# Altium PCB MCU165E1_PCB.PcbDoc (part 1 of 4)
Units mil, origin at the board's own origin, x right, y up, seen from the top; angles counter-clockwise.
Board outline 2658.83 x 2179.35 mil, 6 copper layers (Top Signal Layer, GND1, Mid Layer, PWR, GND2, Bottom Signal Layer), stack 60.4 mil thick; 226 components, 197 nets, 947 pads, 562 vias.
Unrouted connection lines stored in the file: 81.
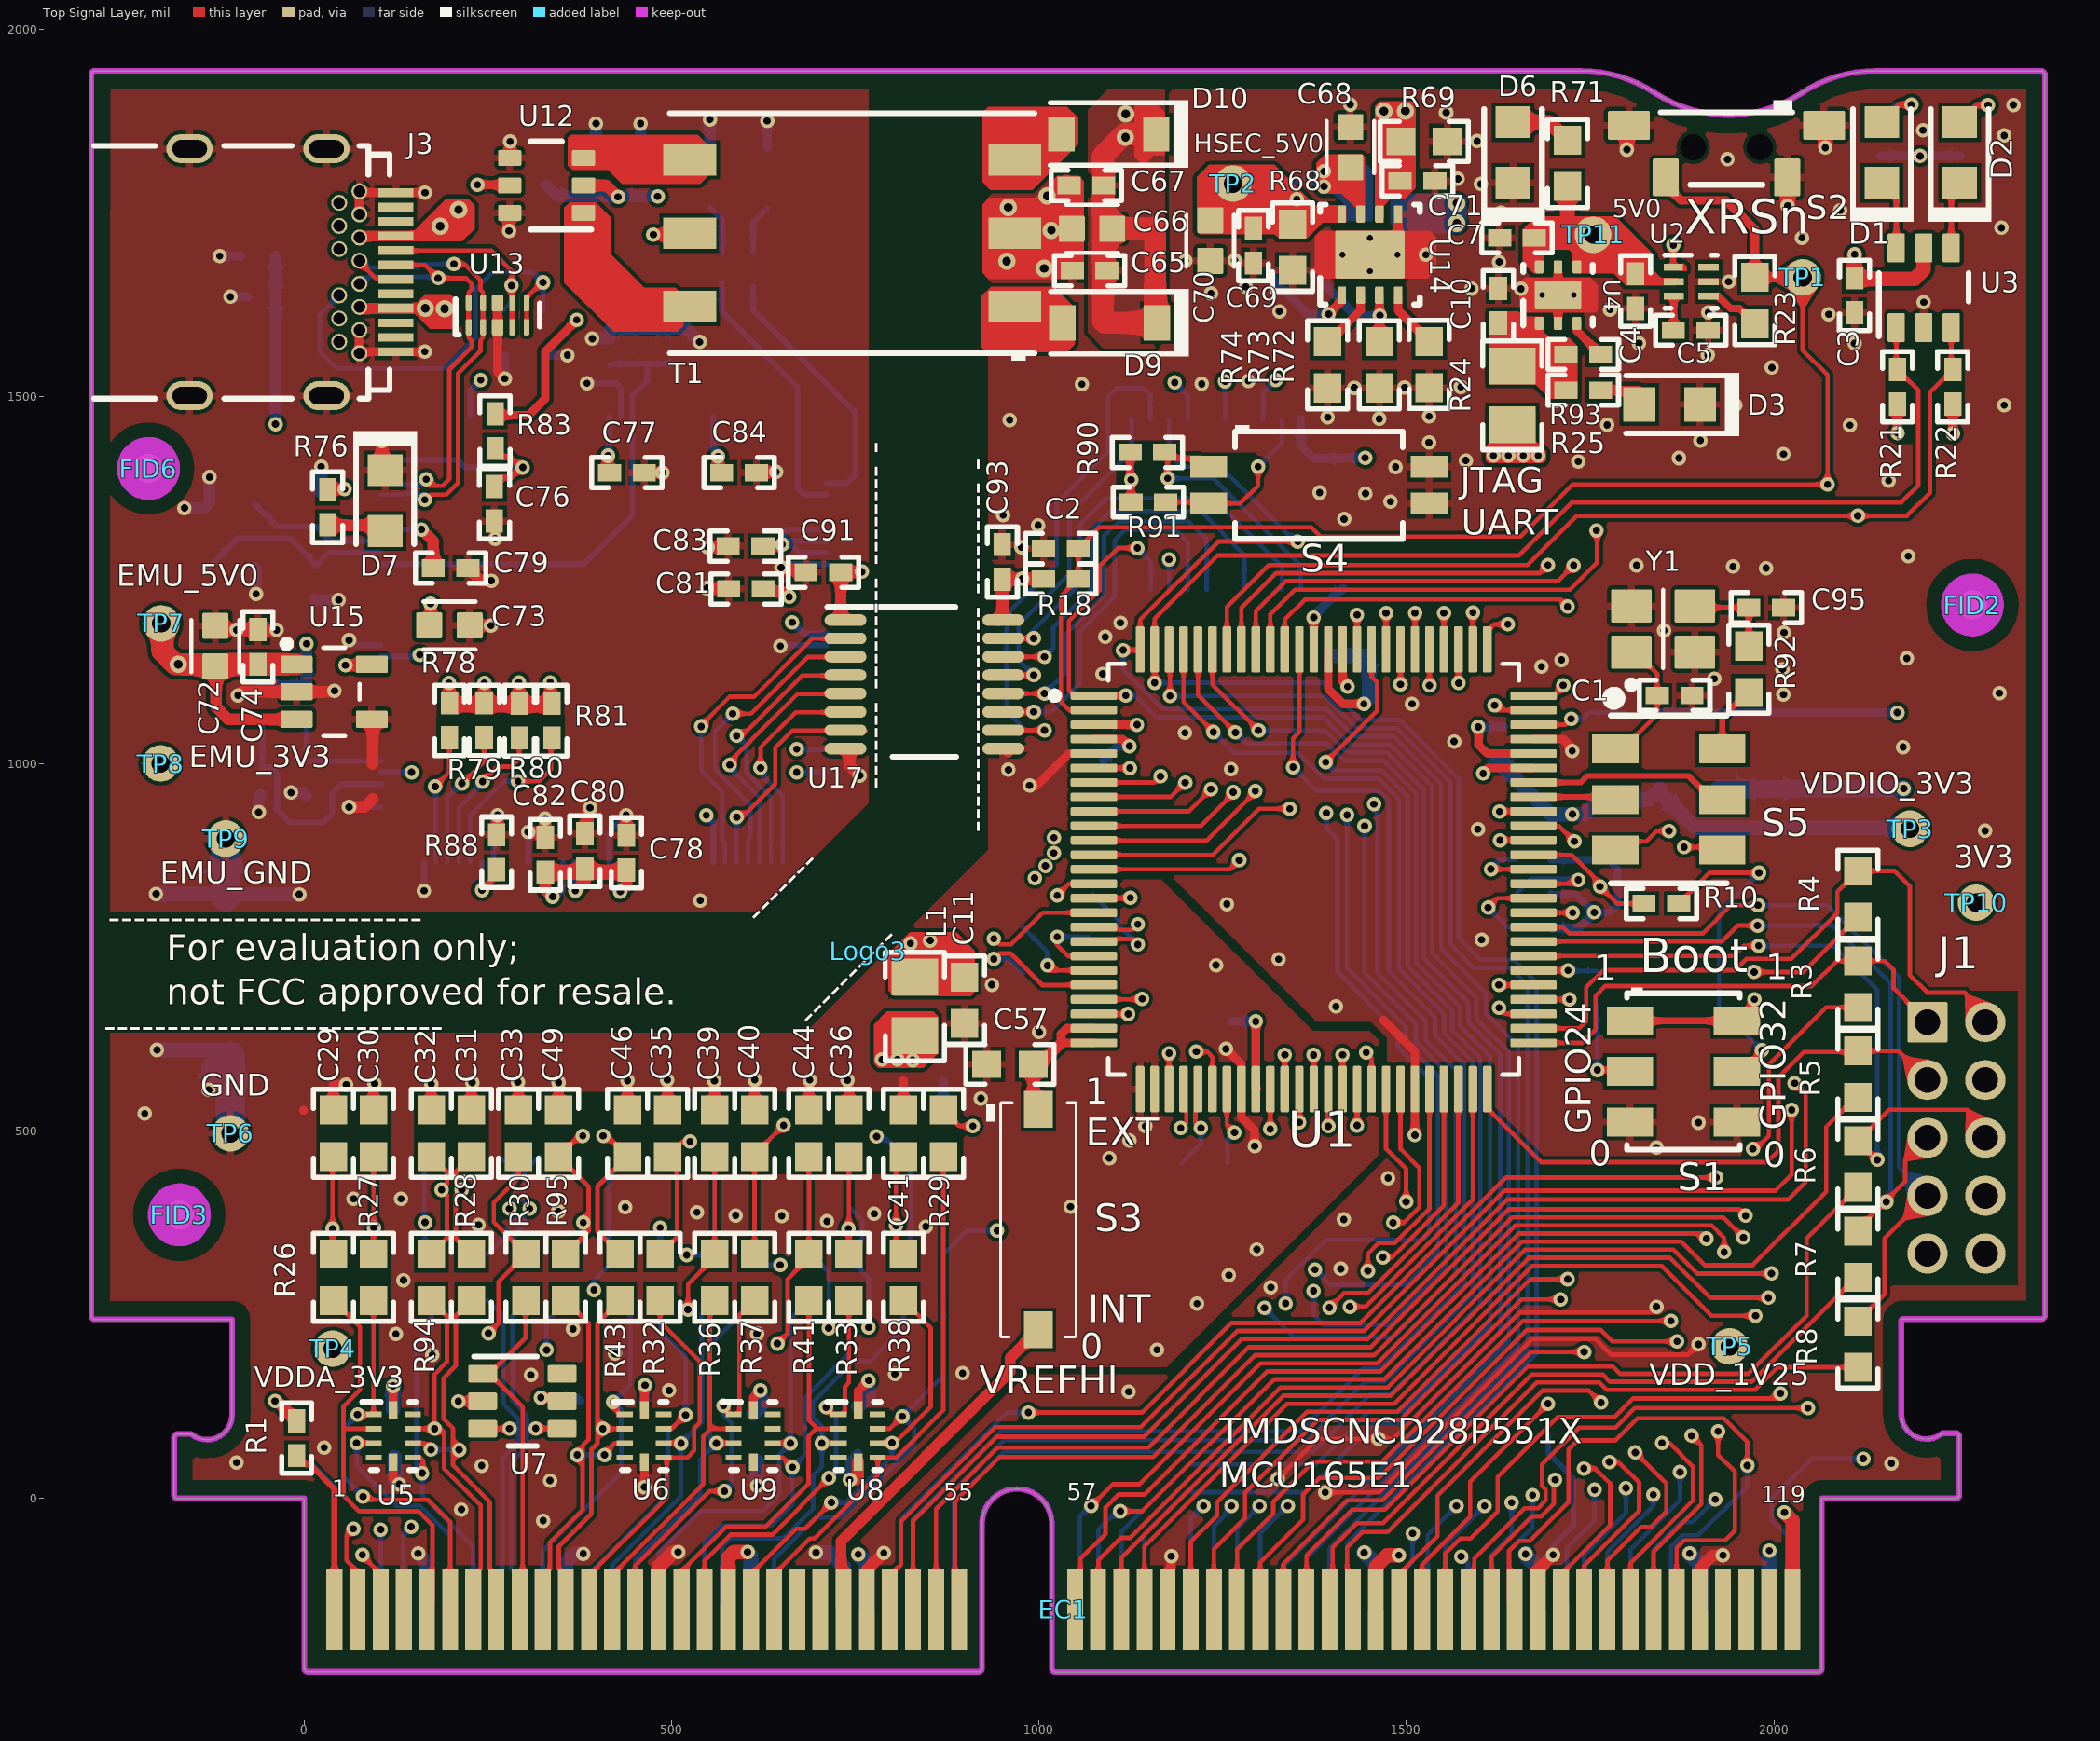
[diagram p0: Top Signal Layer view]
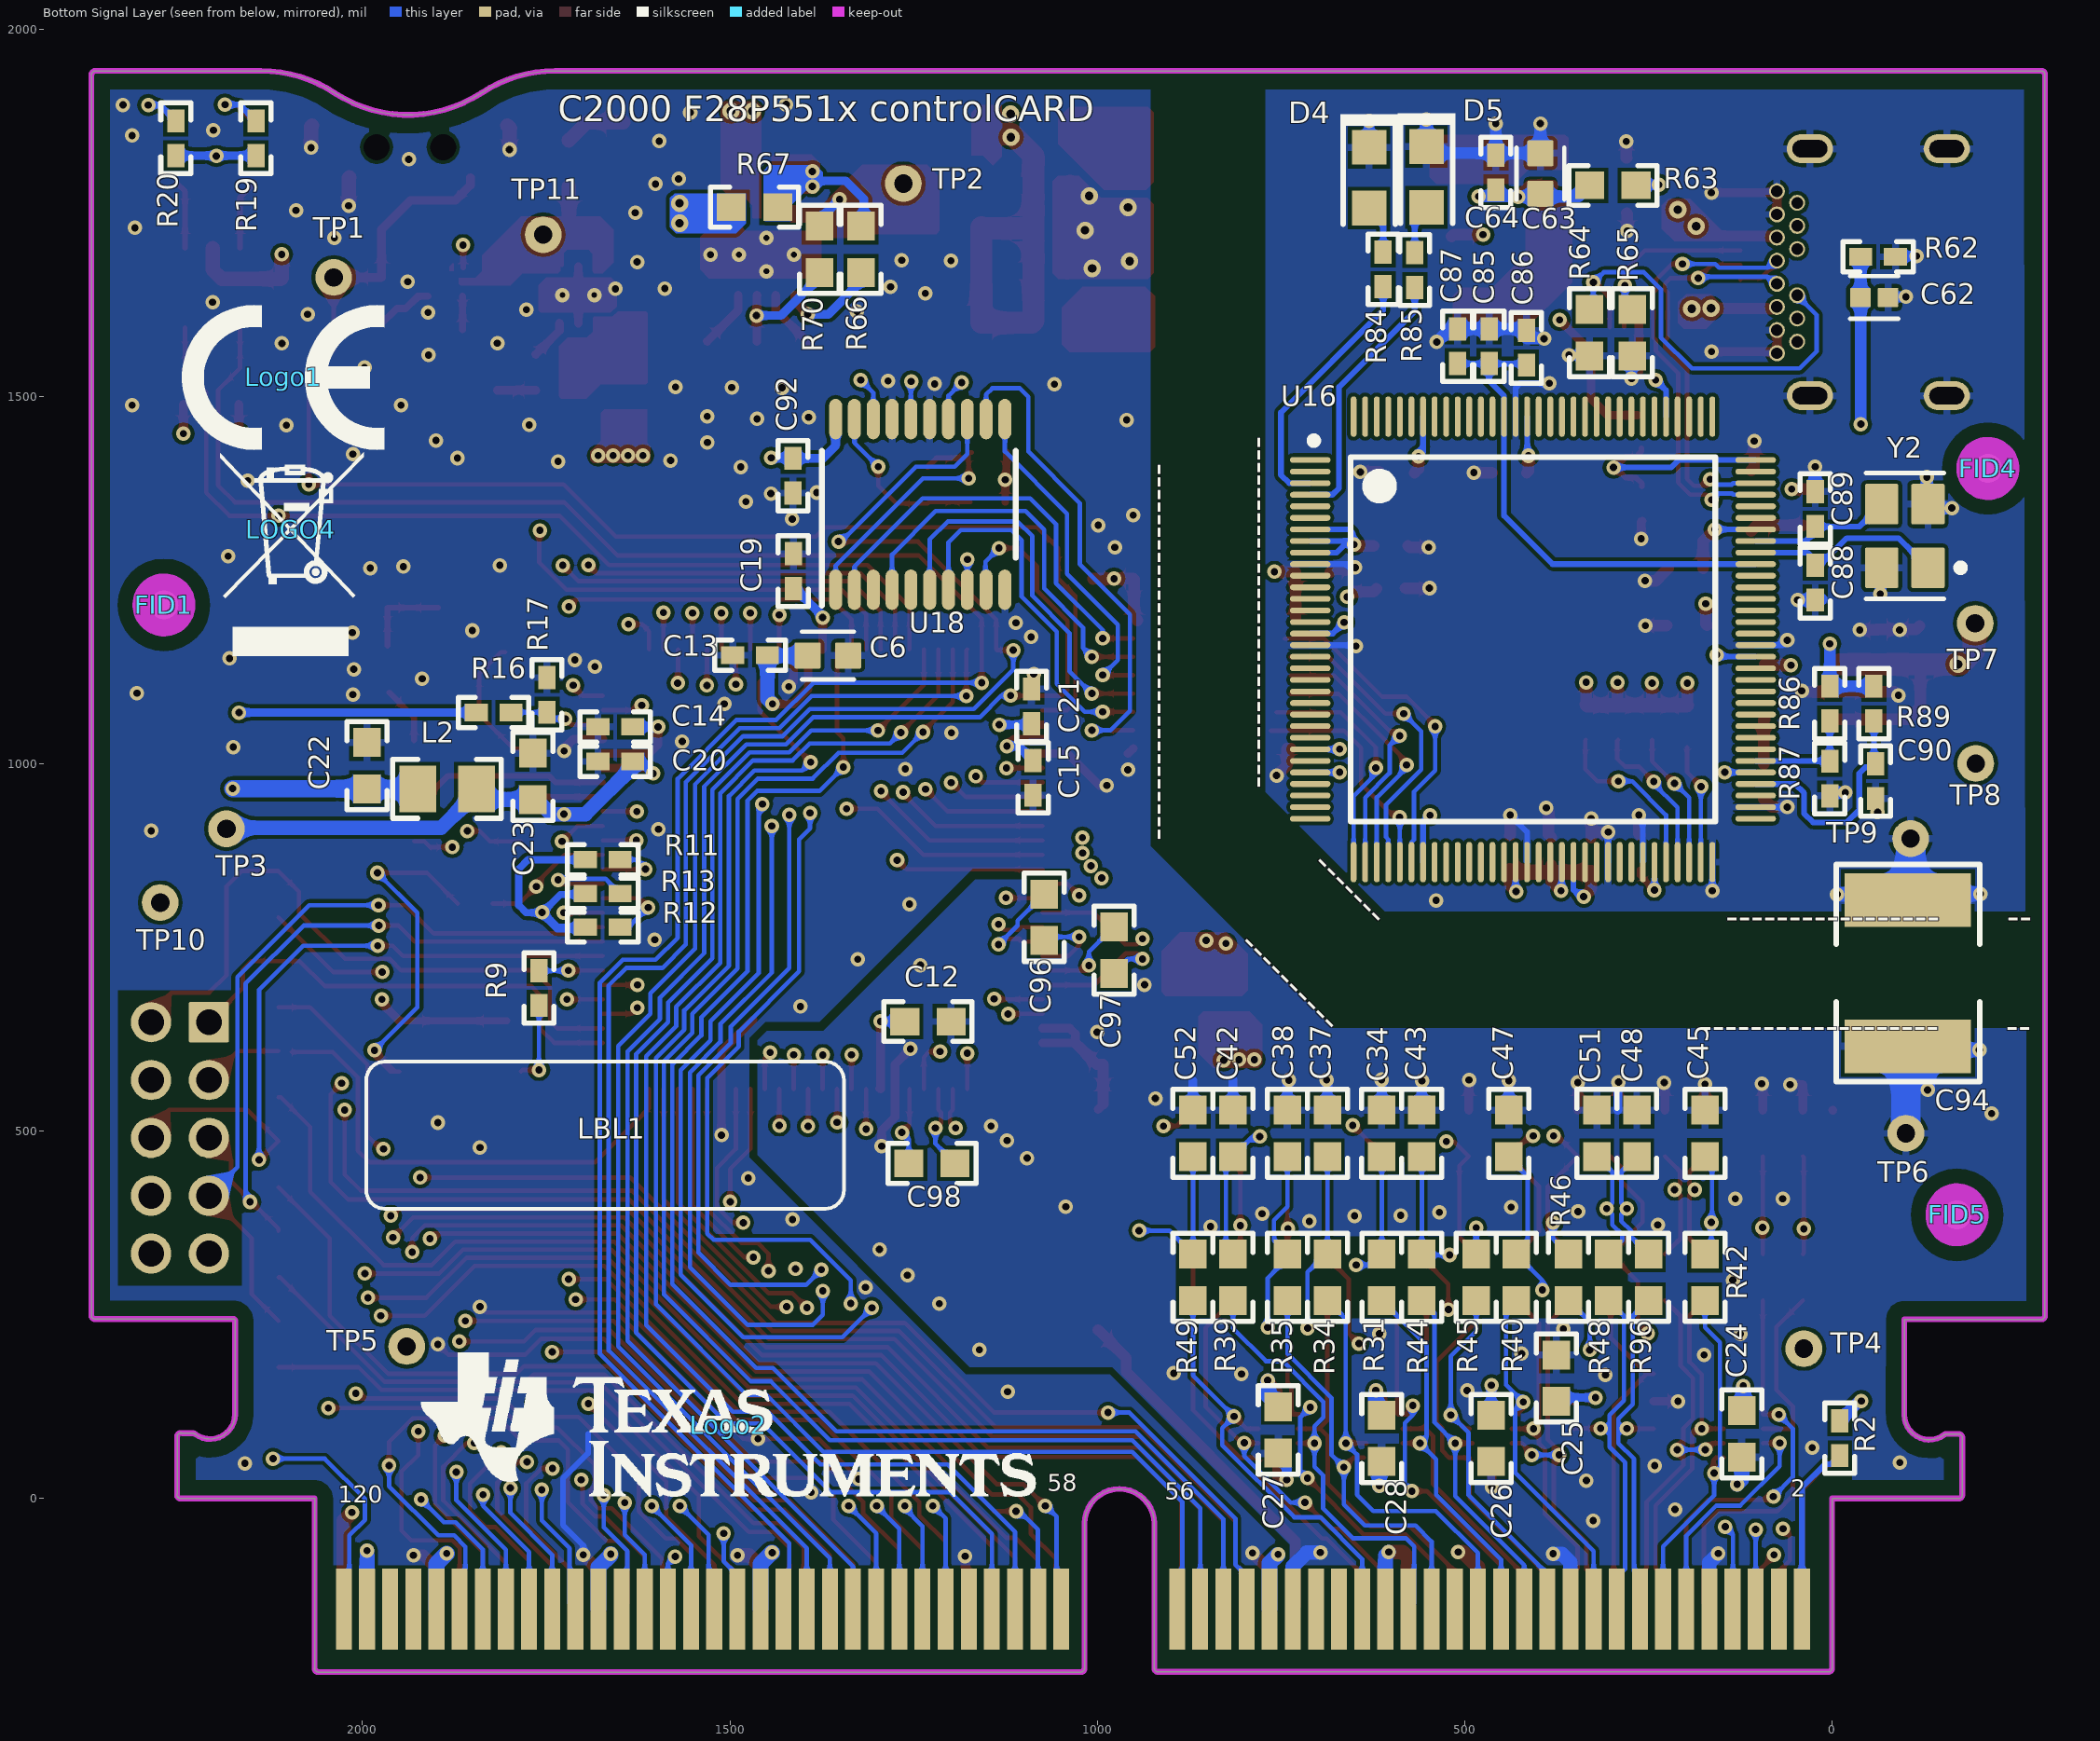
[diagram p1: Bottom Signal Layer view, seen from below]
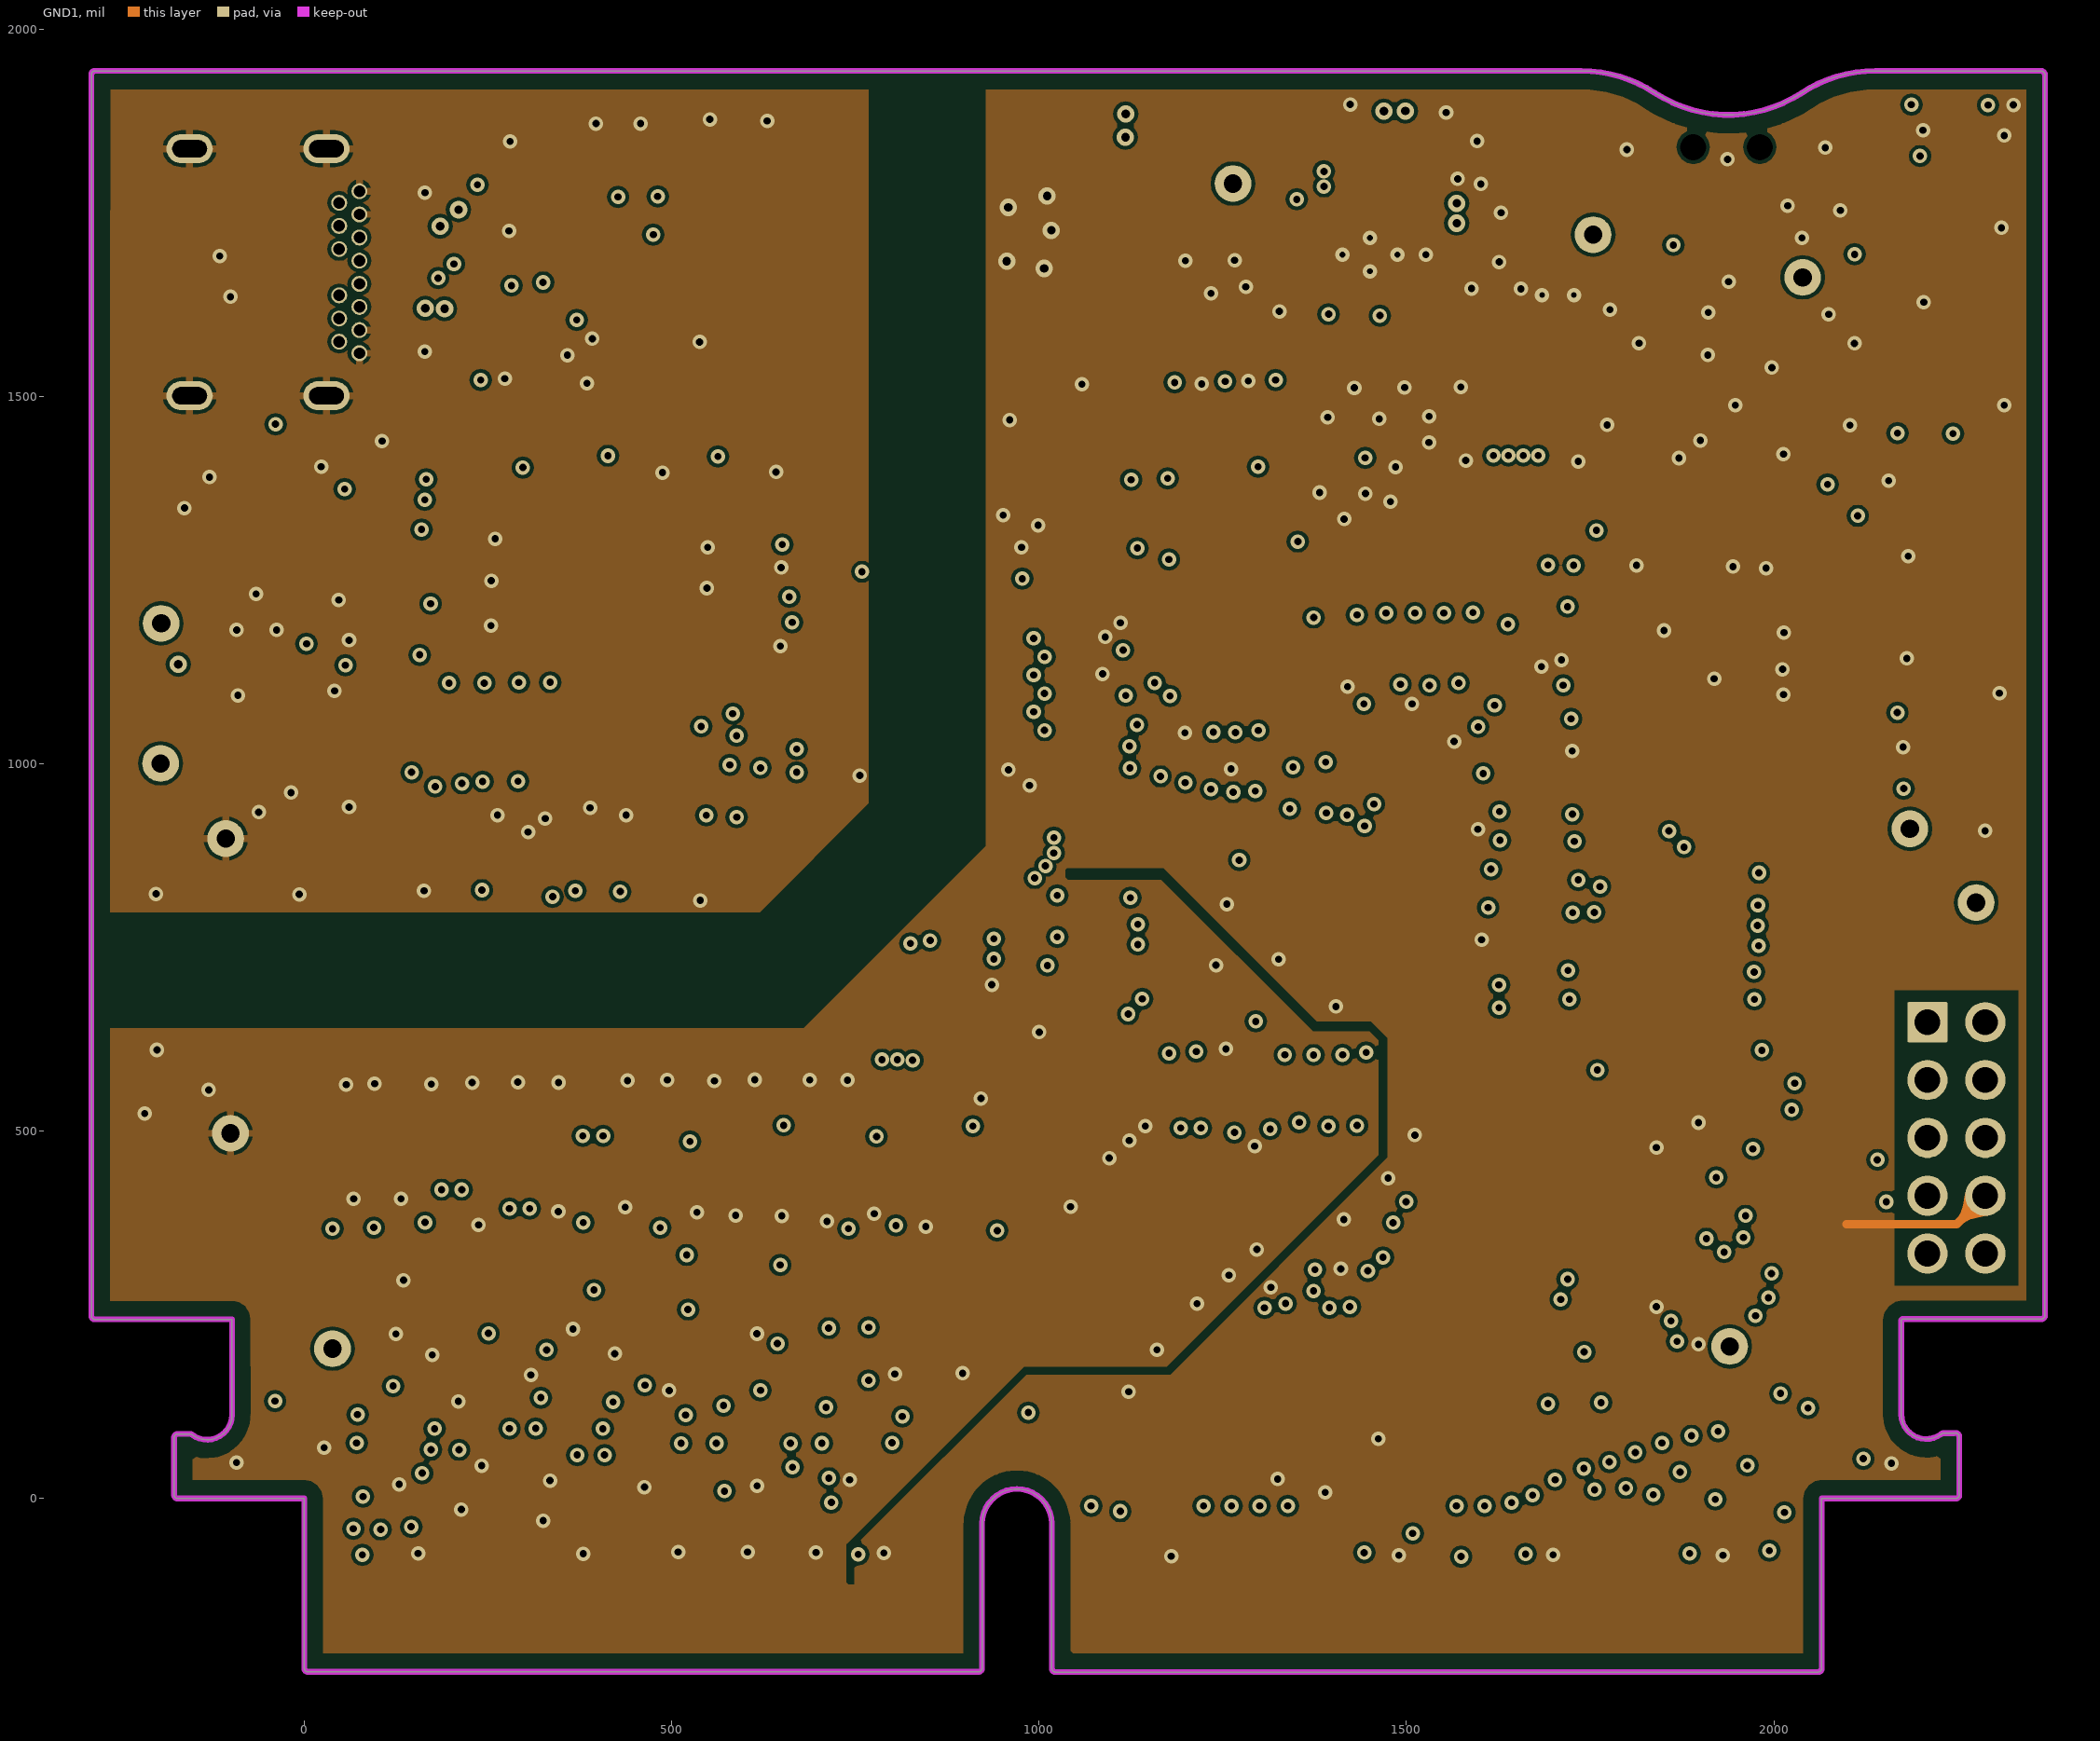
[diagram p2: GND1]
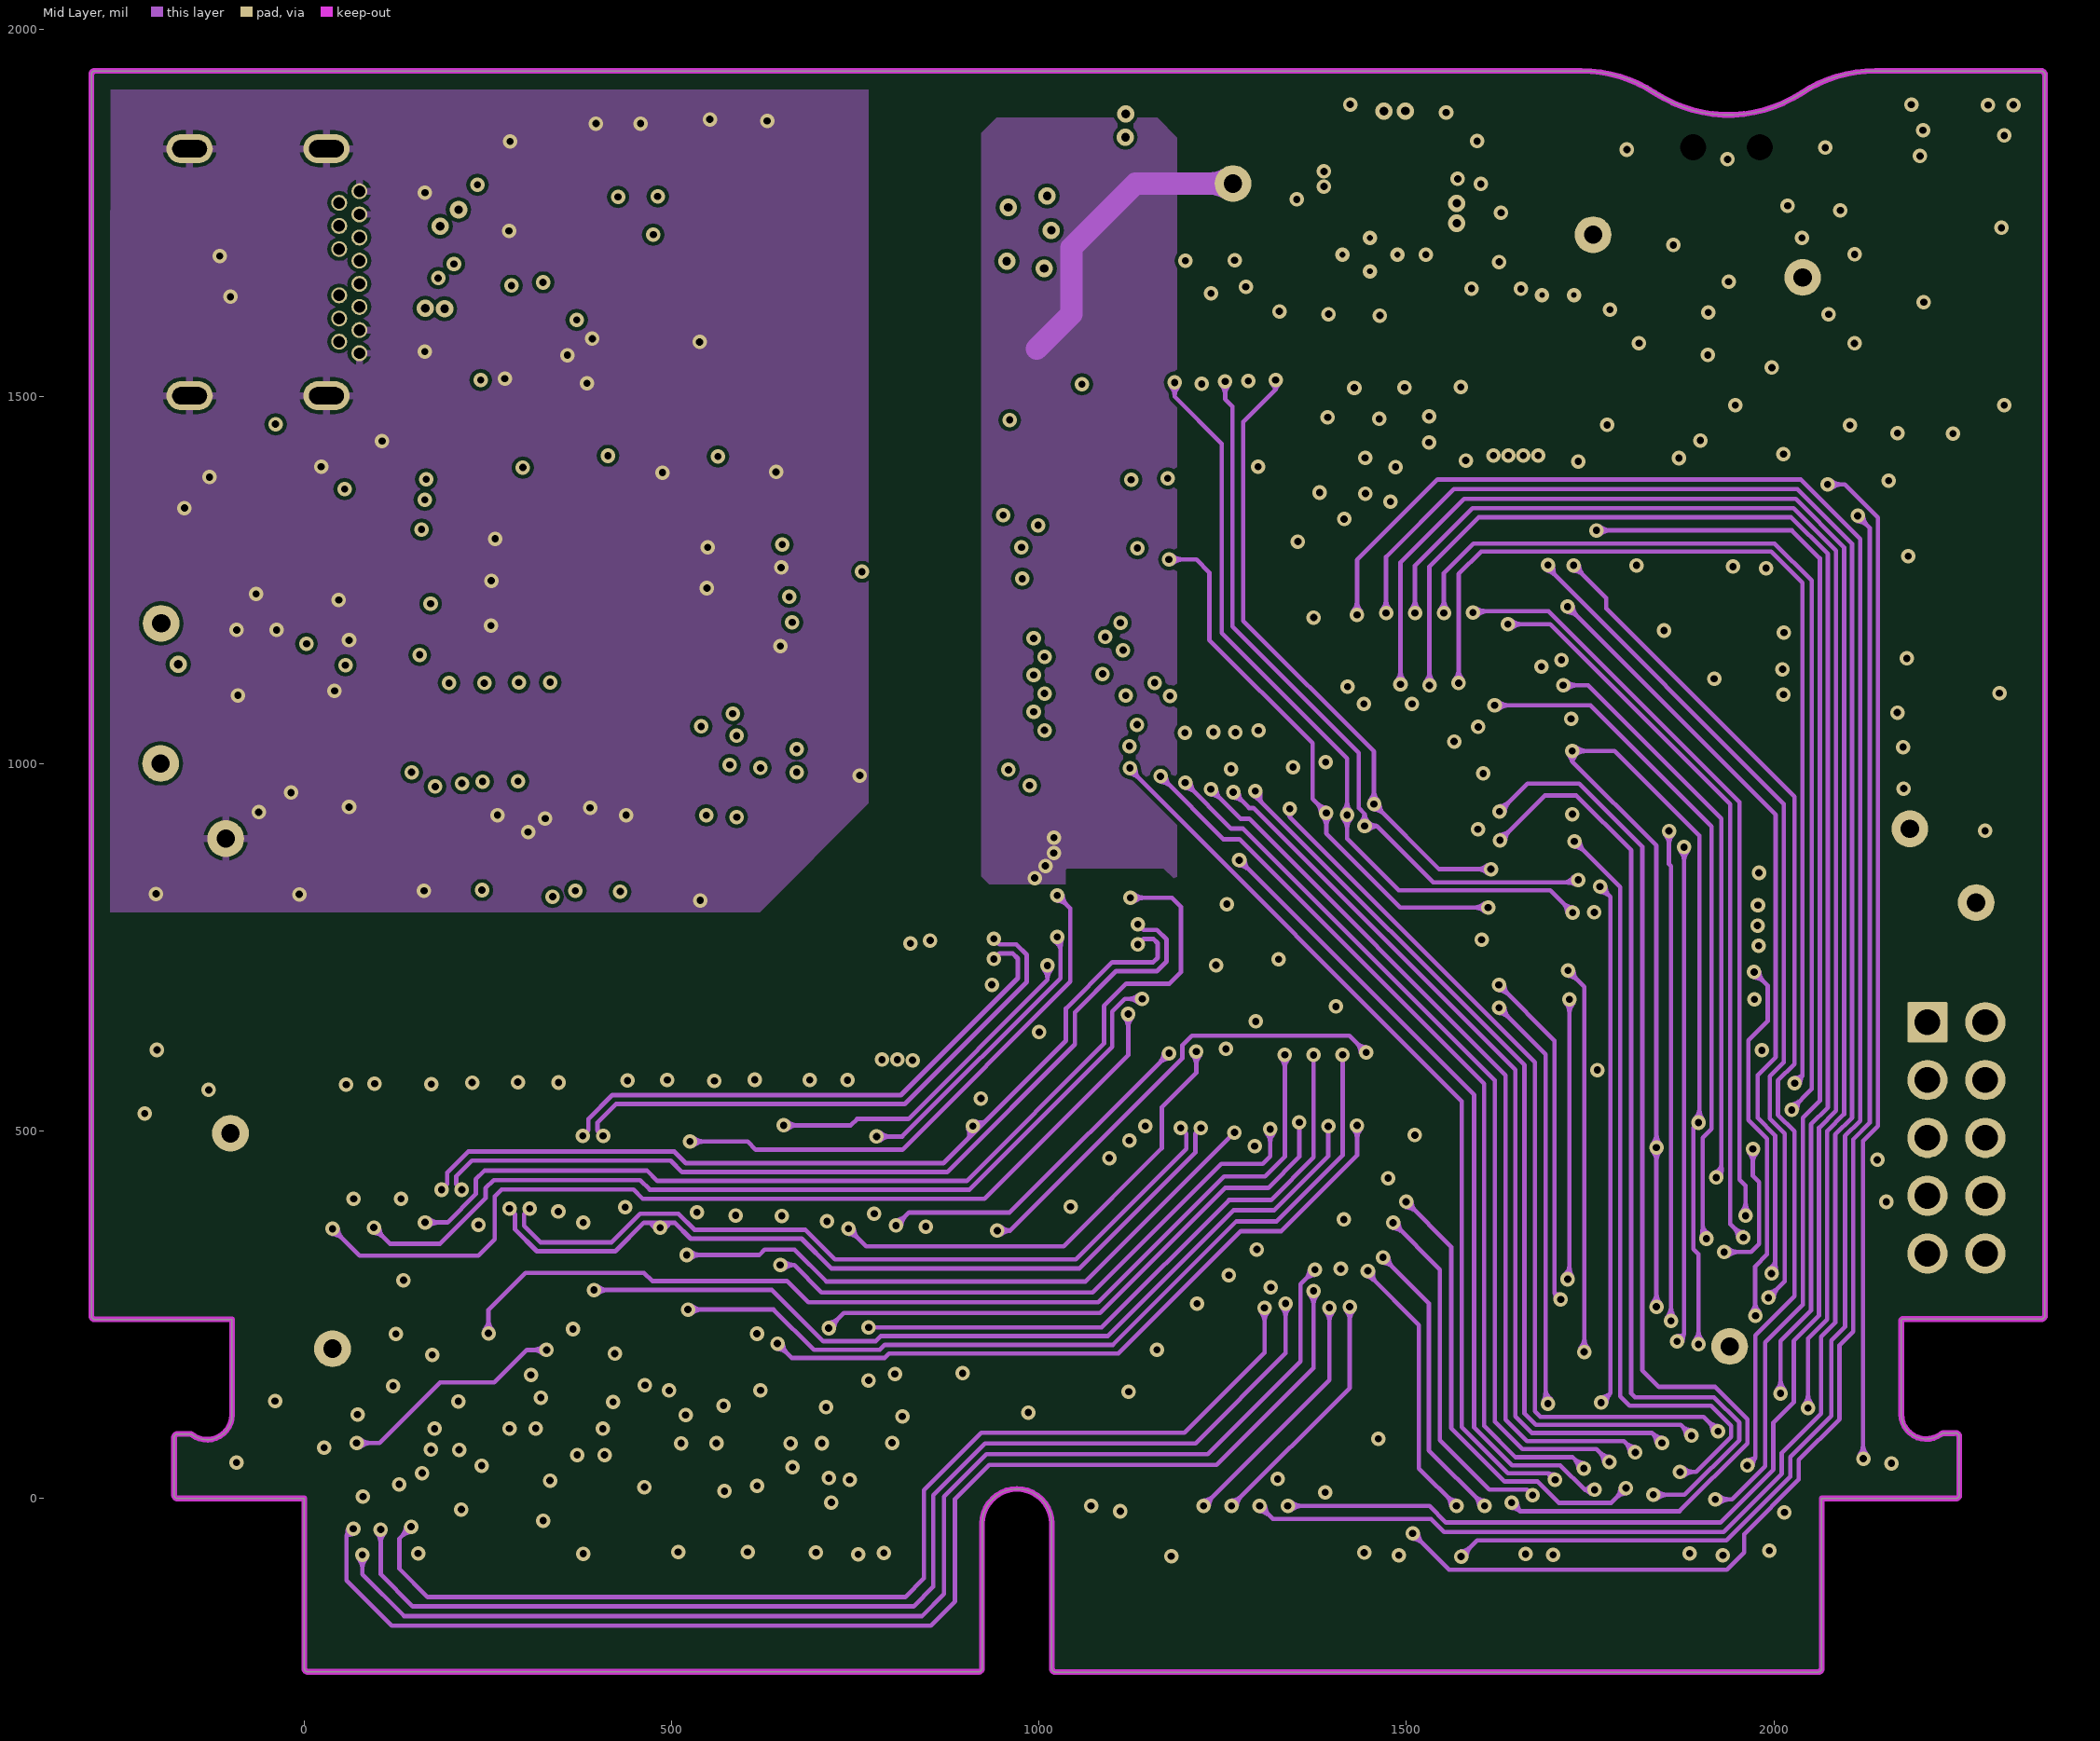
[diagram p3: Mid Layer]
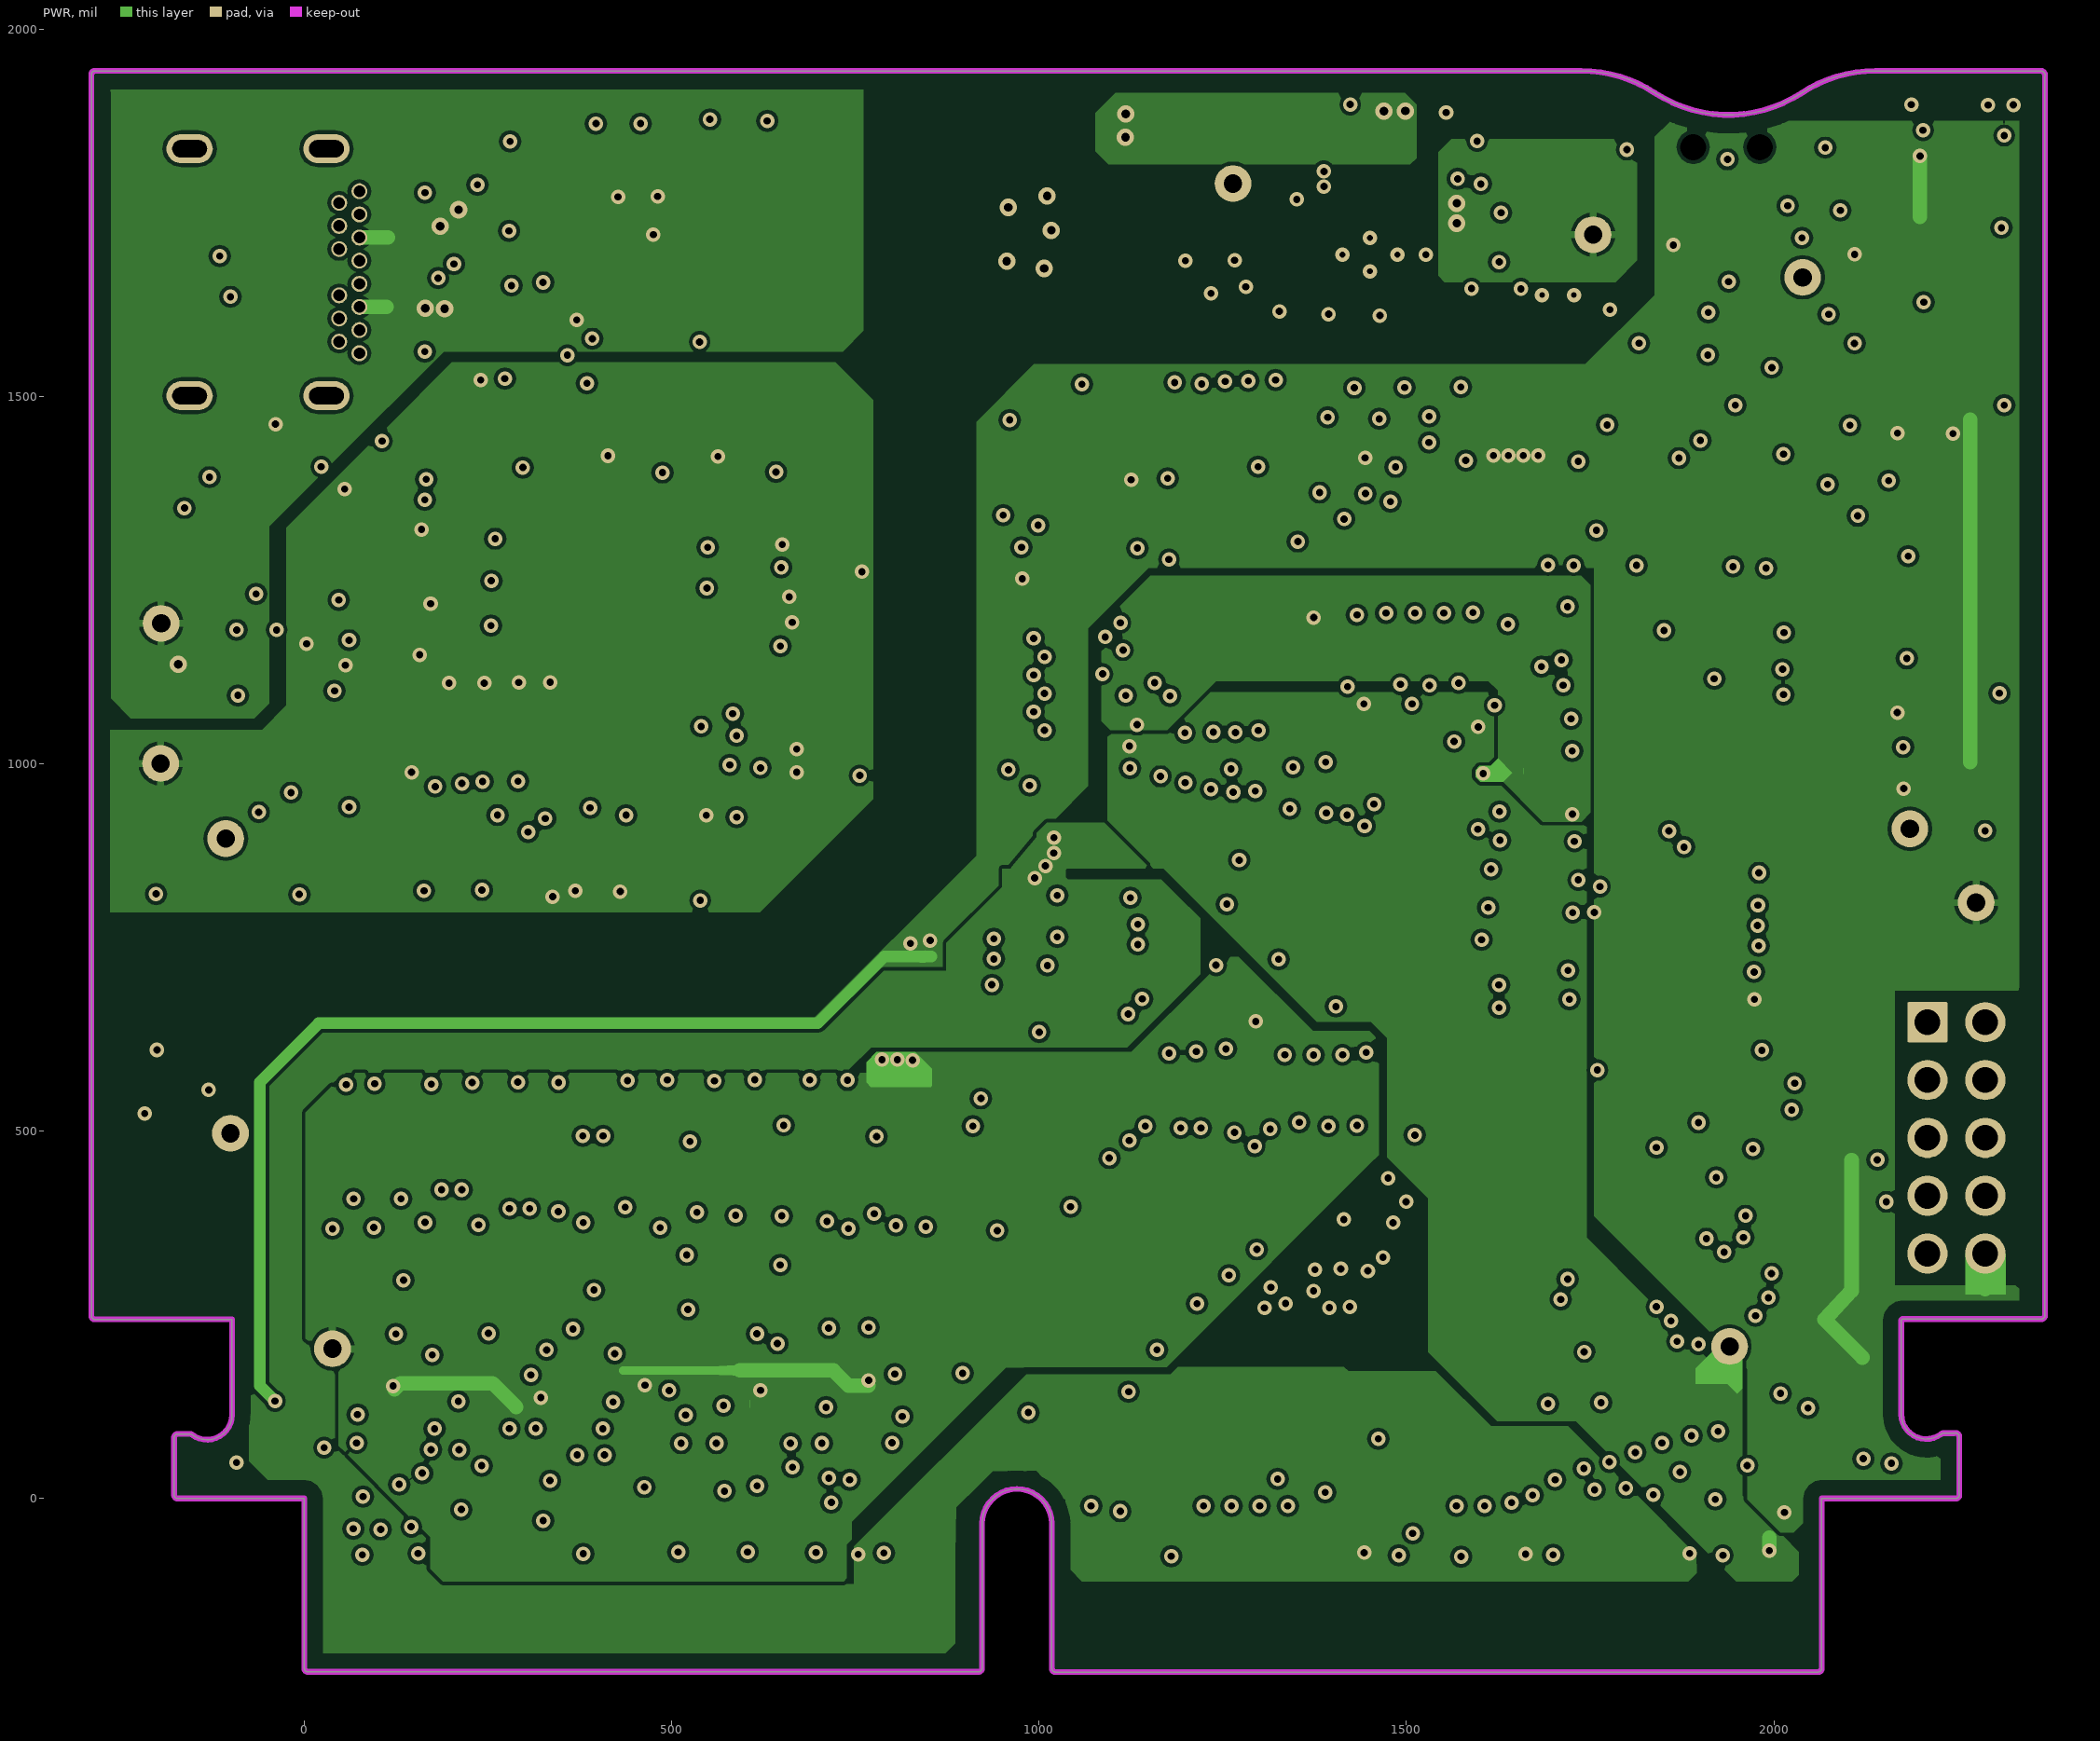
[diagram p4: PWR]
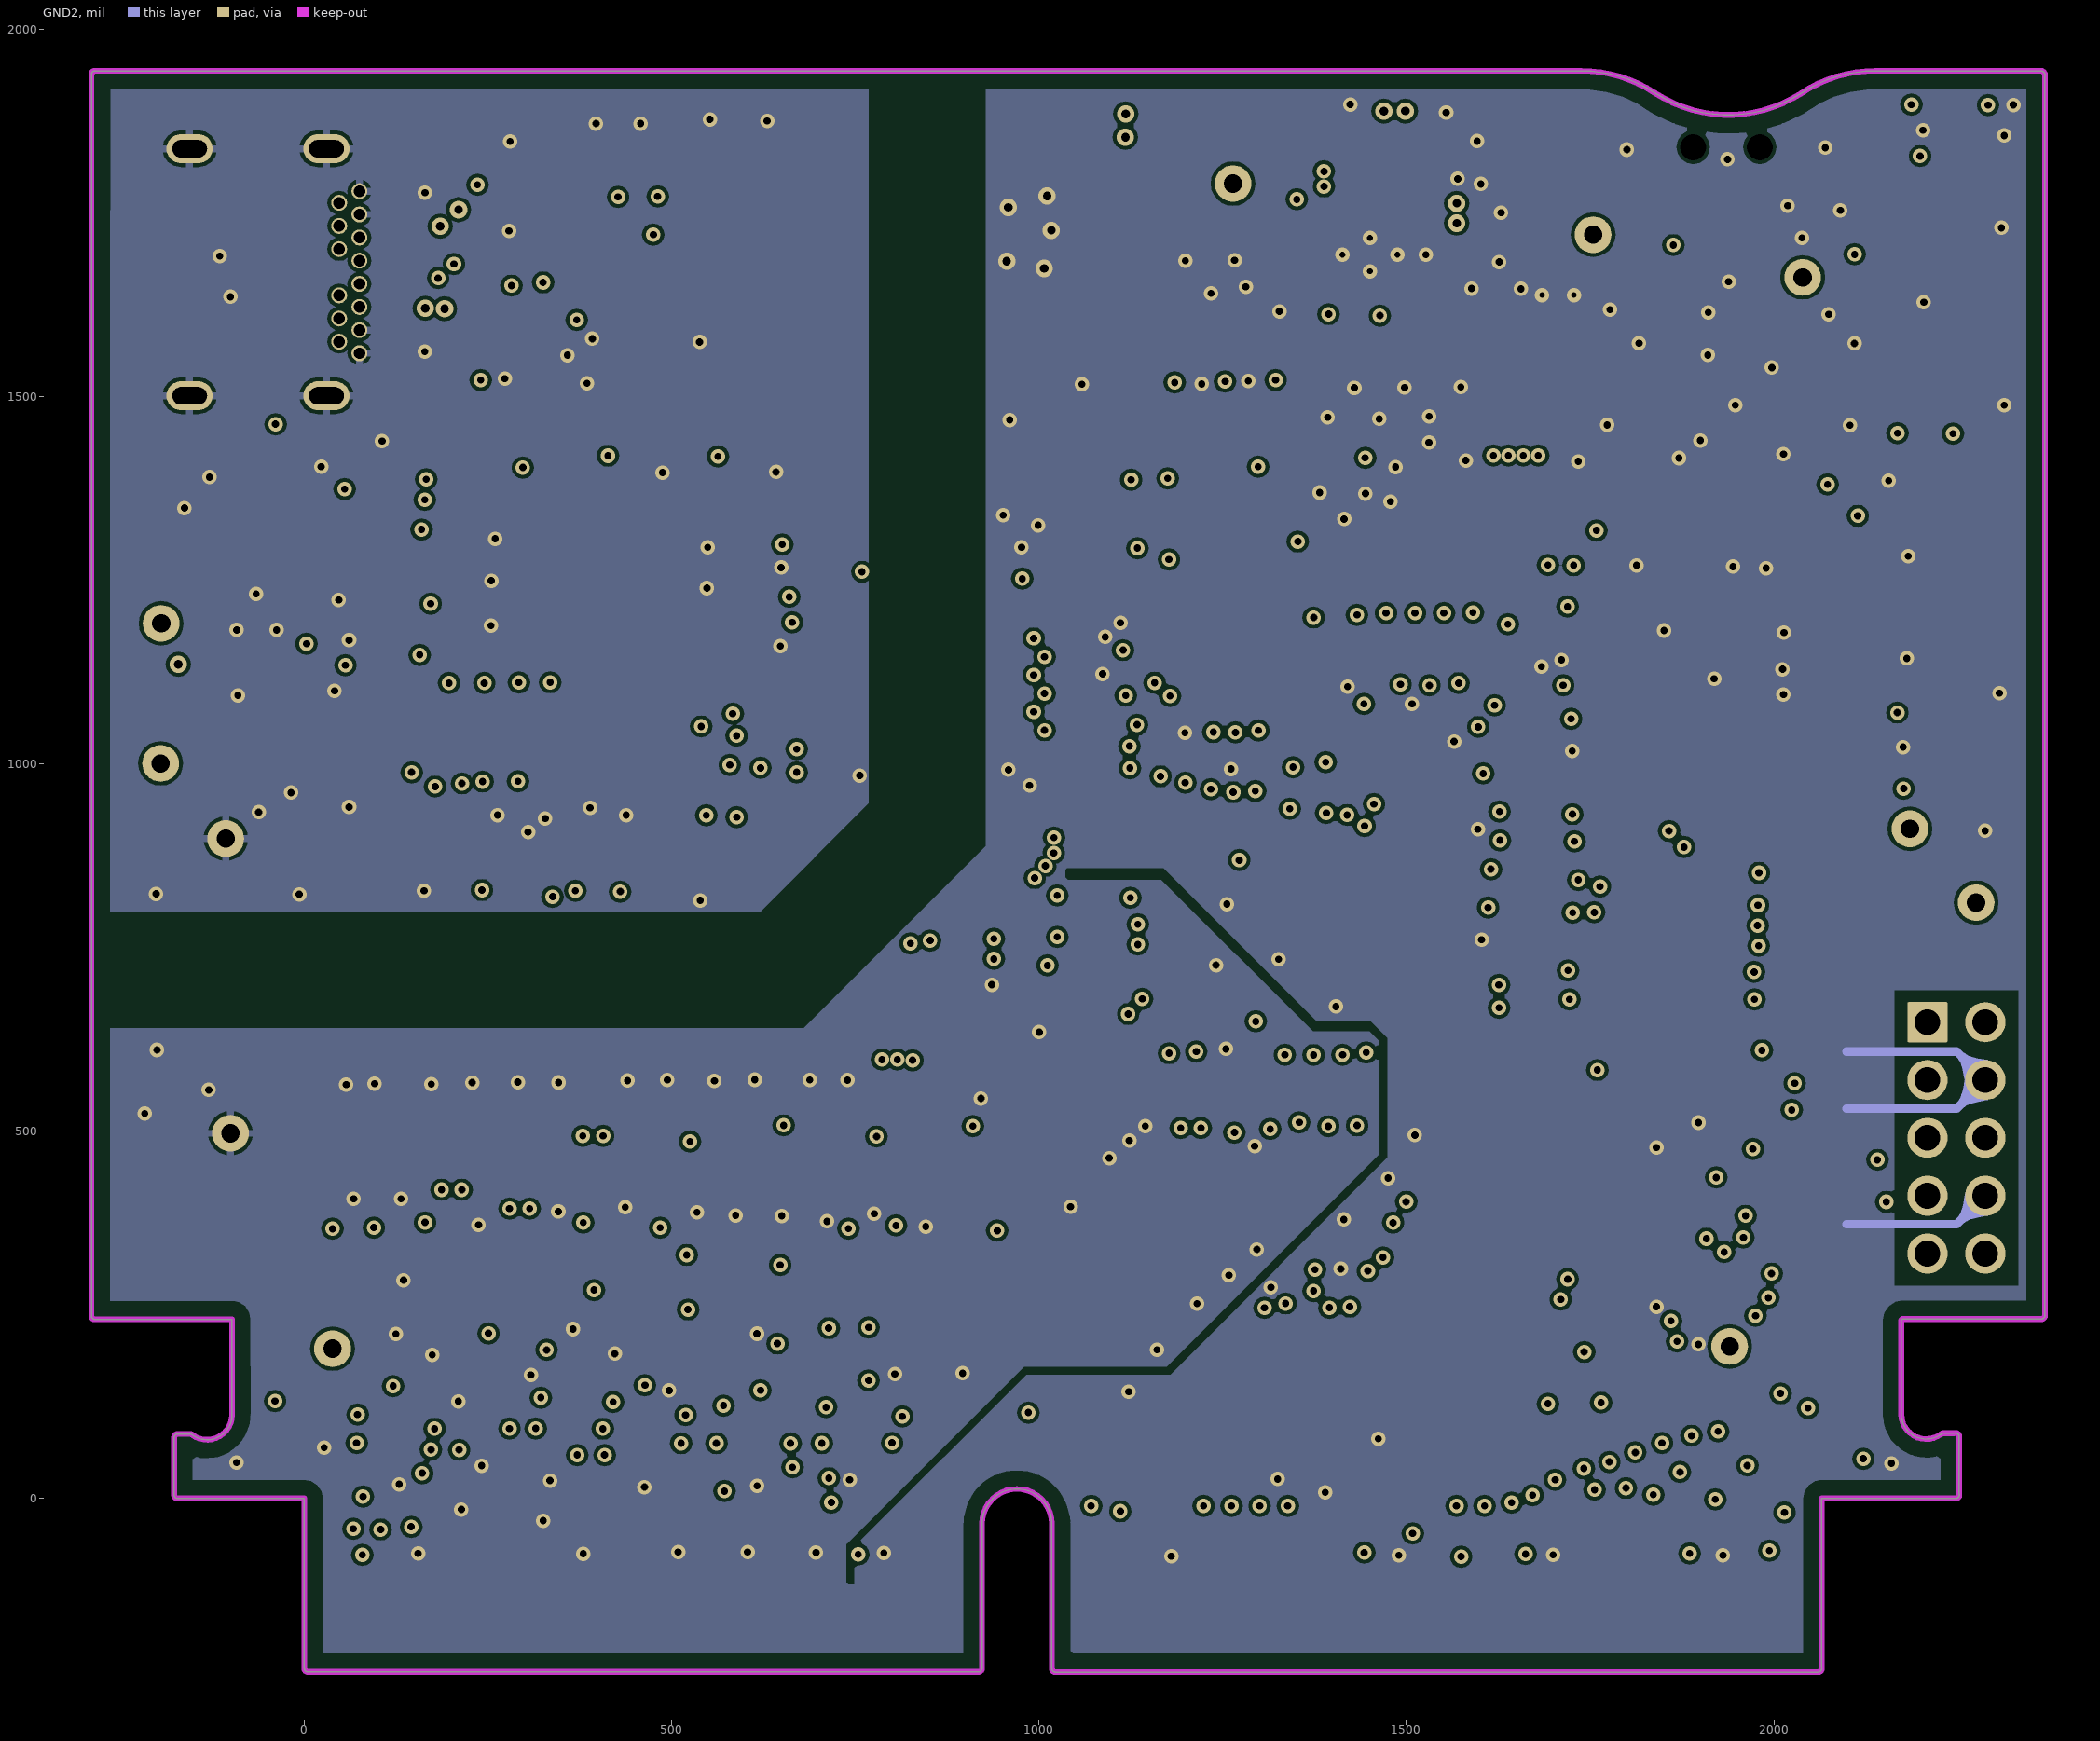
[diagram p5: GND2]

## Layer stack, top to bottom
Top Solder: solder mask 0.7, Solder Resist, Dk 3.5
Top Signal Layer: signal copper 1.4
Dielectric1: prepreg 7, FR-4 High Tg, Dk 4.2
GND1: signal copper 1.4
Dielectric2: core 14, FR-4 High Tg, Dk 4.2
Mid Layer: signal copper 1.4
Dielectric3: prepreg 10, FR-4 High Tg, Dk 4.2
PWR: signal copper 1.4
Dielectric4: core 14, FR-4 High Tg, Dk 4.2
GND2: signal copper 1.4
Dielectric5: prepreg 7, FR-4 High Tg, Dk 4.2
Bottom Signal Layer: signal copper 1.4
Bottom Solder: solder mask 0.7, Solder Resist, Dk 3.5

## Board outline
-171.01,-0.04 0.06,-0.04 0.06,-231.05 ccw(c5.07,-231.05) 5.9,-236 917.4,-236 ccw(c917.4,-230.98) 922.42,-230.98 922.42,-34.1 cw(c969.9,-34.49) 1017.39,-34.1 1017.39,-231.27 ccw(c1022.39,-231.28) 1018.85,-234.82 1018.86,-234.81 ccw(c1022.51,-231.22) 1022.46,-236.35 2060.22,-236.28 ccw(c2060.22,-231.26) 2065.23,-231.26 2065.16,-230.44 2065.16,-0.11 2247.39,-0.11 ccw(c2247.39,4.91) 2252.41,4.91 ccw(c2247.65,4.92) 2252.2,6.32 2252.2,6.33 2252.2,84.13 ccw(c2247.2,84.13) 2245.21,88.73 2245.21,88.74 2230.93,88.74 ccw(c2230.91,83.8) 2227.9,87.72 2227.9,87.73 cw(c2207.4,114.83) 2173.42,114.71 2173.42,242.73 2174.88,244.19 2364,244.19 ccw(c2364,249.2) 2369.01,249.2 2369,249.2 2369,1935.72 ccw(c2362.92,1936.82) 2363.01,1943 2138,1942.99 2138,1943 ccw(c2138,1761.33) 2038,1913 cw(c1938,2064.67) 1838,1913 ccw(c1738,1761.33) 1738,1943 1737,1943 -284.72,1942.99 -284.72,1943.01 ccw(c-284.72,1937.99) -289.73,1937.99 -289.73,248.71 ccw(c-284.72,248.71) -284.72,243.7 -98.32,243.7 -98.32,115.84 cw(c-124,114.26) -98.27,113.93 cw(c-132.25,113.92) -152.76,86.83 ccw(c-155.74,82.96) -155.78,87.84 -172.11,87.84 ccw(c-172.15,82.91) -175.66,86.37 ccw(c-172.11,82.73) -177.19,82.76 -177.19,4.84 ccw(c-172.19,4.83)

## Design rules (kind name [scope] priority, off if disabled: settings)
AcuteAngle [Not IsPoly] p1: minimum=4.50000000000000E+0001 checktracksonly=FALSE
AssemblyTestPointUsage [All] p1: valid=2
BoardOutlineClearance BoardOutlineClearance_MountingHoles [OnCopper and InComponentClass('Mounting Holes')] p1: gap=40 ignorepadtopadclearanceinfootprint=FALSE
BoardOutlineClearance BoardOutlineClearance_Poly [OnCopper and IsPoly] p2: gap=25 ignorepadtopadclearanceinfootprint=FALSE
BoardOutlineClearance [OnCopper and Not InComponentClass('Logo') and not InComponentClass('FiducialMark') and not InComponent ('EC1') and not InPoly and not InRegion(-350,-150,2400,2025) and not HasPad('S2-1')AND NOT HasPad('S2-2')] p3: gap=40 ignorepadtopadclearanceinfootprint=FALSE except(30: Arc-OutlineEdge Track-OutlineEdge SMDPad-OutlineEdge THPad-OutlineEdge Via-OutlineEdge Fill-OutlineEdge Poly-OutlineEdge Region-OutlineEdge Text-OutlineEdge)
Clearance isvia [IsVia vs isvia] p1: gap=7.87 ignorepadtopadclearanceinfootprint=TRUE
Clearance Clearance_Keepouts [((IsTrack Or IsArc) And Not InPoly) And IsFree and IsKeepOut vs ((IsTrack Or IsArc) And Not InPoly) And IsFree and IsKeepOut] p2: gap=0 ignorepadtopadclearanceinfootprint=FALSE
Clearance Clearance_Boardedge_MountingHole [OnCopper and InComponentClass('Mounting Holes') vs IsKeepOut] p3: gap=19.68 ignorepadtopadclearanceinfootprint=FALSE
Clearance Clearance_Boardedge_Poly_1 [InPoly vs IsKeepOut] p4: gap=19.68 ignorepadtopadclearanceinfootprint=FALSE
Clearance Clearance_Boardedge_Poly [OnCopper and InPoly vs IsKeepOut] p5: gap=25 ignorepadtopadclearanceinfootprint=FALSE except(0: SMDPad-Hole THPad-Hole Via-Hole Fill-Hole Poly-Hole Region-Hole Text-Hole; 3: Arc-Fill Arc-Poly Arc-Region Track-Fill Track-Poly Track-Region)
Clearance Clearance_Boardedge [OnCopper and Not InComponentClass('Logo') and not InComponentClass('FiducialMark') and not Incomponent ('EC1') and not IsKeepout vs IsKeepOut] p6: gap=10 ignorepadtopadclearanceinfootprint=FALSE except(0: Arc-Hole Track-Hole SMDPad-Hole THPad-Hole Via-Hole Fill-Hole Poly-Hole Region-Hole Text-Hole; 2.5: Arc-Arc Arc-Track Arc-SMDPad Track-Track Track-SMDPad)
Clearance Clearance_Poly [InPolygon] p7: gap=5 ignorepadtopadclearanceinfootprint=FALSE
Clearance Clearance_Fiducial [HasFootprint('Fiducial10-20')] p8: gap=4 ignorepadtopadclearanceinfootprint=TRUE except(0: Arc-SMDPad Arc-Hole Track-Hole SMDPad-Hole THPad-Hole Via-Hole Fill-Hole Poly-Hole Region-Hole Text-Hole)
Clearance Clearance_to_TH [OnLayer('Top Layer') Or OnLayer('Bottom Layer')] p9: gap=4 ignorepadtopadclearanceinfootprint=TRUE except(0: Arc-Hole Track-Hole SMDPad-Hole THPad-Hole Via-Hole Fill-Hole Poly-Hole Region-Hole Text-Hole; 7: Arc-THPad Track-THPad SMDPad-THPad THPad-THPad THPad-Via THPad-Fill THPad-Poly THPad-Region THPad-Text)
Clearance [All] p10: gap=5 ignorepadtopadclearanceinfootprint=TRUE
ComponentClearance ComponentClearance_MountingHoles_FiducialMarks [InComponentClass('Mounting Holes') vs InComponentClass('FiducialMark')] p1 off: gap=50 collisioncheckmode=3 verticalgap=10 showdistances=FALSE
ComponentClearance ComponentClearance_Shunt [InComponentClass('Header') vs InComponentClass('Shunt')] p2 off: gap=0 collisioncheckmode=3 verticalgap=0 showdistances=FALSE
ComponentClearance ComponentClearance_Logo [InComponentClass('Logo')] p3 off: gap=40 collisioncheckmode=3 verticalgap=10 showdistances=FALSE
ComponentClearance ComponentClearance_ScrewToNut [(HasFootprint('NY PMS 440 0025 PH')) vs (HasFootprint('Keystone_1902C'))] p4 off: gap=5 collisioncheckmode=3 verticalgap=10 showdistances=FALSE
ComponentClearance ComponentClearance_MountingHoles [InComponentClass('Mounting Holes')] p5 off: gap=250 collisioncheckmode=3 verticalgap=100000 showdistances=FALSE
ComponentClearance ComponentClearance_SmallPassives [HasFootprint('0201*') or HasFootprint('0402*') or HasFootprint('0508') or HasFootprint('0603*') or HasFootprint('0612') or HasFootprint('0805*') or HasFootprint('0815*') or HasFootprint('0830*') or HasFootprint('1206*') or HasFootprint('1210*') or HasFootprint('1808*') or HasFootprint('1812*') or HasFootprint('1825*') or HasFootprint('2010*') or HasFootprint('2220*') or HasFootprint('2225*') or HasFootprint('2512*') or HasFootprint('2728*') or HasFootprint('3518*')  or HasFootprint('*0402-IPC*') vs HasFootprint('0201*') or HasFootprint('0402*') or HasFootprint('0508') or HasFootprint('0603*') or HasFootprint('0612') or HasFootprint('0805*') or HasFootprint('0815*') or HasFootprint('0830*') or HasFootprint('1206*') or HasFootprint('1210*') or HasFootprint('1808*') or HasFootprint('1812*') or HasFootprint('1825*') or HasFootprint('2010*') or HasFootprint('2220*') or HasFootprint('2225*') or HasFootprint('2512*') or HasFootprint('2728*') or HasFootprint('3518*') or HasFootprint('*0402-IPC*')] p6 off: gap=10 collisioncheckmode=3 verticalgap=10 showdistances=FALSE
ComponentClearance ComponentClearance_THtoSMT [IsThruComponent vs IsSMTComponent and not Incomponent ('J1') and not Incomponent ('J2') and not Incomponent ('J3') and not Incomponent ('J4')] p7 off: gap=40 collisioncheckmode=3 verticalgap=30 showdistances=FALSE
ComponentClearance ComponentClearance_THtoTH [IsThruComponent vs IsThruComponent] p8 off: gap=30 collisioncheckmode=3 verticalgap=30 showdistances=FALSE
ComponentClearance [All] p9 off: gap=30 collisioncheckmode=3 verticalgap=10 showdistances=FALSE
DiffPairsRouting [All] p1: maxlimit=6 minlimit=6 mostfreqgap=6 toplayer_minwidth=6.1 toplayer_maxwidth=6.2 toplayer_prefwidth=6.1 midlayer1_minwidth=6.1 midlayer1_maxwidth=6.2 midlayer1_prefwidth=6.1 midlayer2_minwidth=6.1 midlayer2_maxwidth=6.2 midlayer2_prefwidth=6.1 midlayer3_minwidth=6.1 midlayer3_maxwidth=6.2 midlayer3_prefwidth=6.1 midlayer4_minwidth=6.1 midlayer4_maxwidth=6.2 midlayer4_prefwidth=6.1 bottomlayer_minwidth=6.1 bottomlayer_maxwidth=6.2 bottomlayer_prefwidth=6.1 maxuncoupledlength=1000
FabricationTestPointUsage TestPointUsage [All] p1: valid=2 allowmultiple=FALSE
FabricationTestpoint Testpoint [All] p1: side=3 testpointundercomponent=TRUE minsize=40 maxsize=100 preferedsize=60 minholesize=0 maxholesize=40 preferedholesize=32 testpointgrid=1 allowsidetop=TRUE allowsidebottom=TRUE usegrid=TRUE gridtolerance=0.01
FanoutControl Fanout_LCC [IsLCC] p1: bgadir=Out bgaviamode=Centered fanoutstyle=Auto fanoutdirection=Alternating viagrid=1 // Fanout_LCC (Default Rule)
FanoutControl Fanout_BGA [IsBGA] p2: bgadir=Out bgaviamode=Centered fanoutstyle=Auto fanoutdirection=Alternating viagrid=1 // Fanout_BGA (Default Rule)
FanoutControl Fanout_Default [All] p4: bgadir=Out bgaviamode=Centered fanoutstyle=Auto fanoutdirection=Alternating viagrid=1 // Fanout_Default (Default Rule)
FanoutControl Fanout_Small [(CompPinCount < 5)] p5: bgadir=Out bgaviamode=Centered fanoutstyle=Auto fanoutdirection=OutThenIn viagrid=1 // Fanout_Small (Default Rule)
Height [All] p1 off: minheight=0 maxheight=1000 prefheight=500
HoleSize [All] p1: absolutevalues=TRUE maxlimit=251 minlimit=7.87 maxpercent=80.000 minpercent=20.000
MinimumAnnularRing MinimumAnnularRing_ThermalPadVias [IsVia and InAnyComponent] p1 off: minimumring=5.91
MinimumAnnularRing [All] p2 off: minimumring=3.94
MinimumSolderMaskSliver MinimumSolderMaskSliver_Logo [InComponentClass('Logo') vs InComponentClass('Logo')] p1: minsoldermaskwidth=0.7
MinimumSolderMaskSliver [All] p2: minsoldermaskwidth=3.94
PlaneClearance PlaneClearance_1 [All] p1: clearance=10
PlaneClearance PlaneClearance_Via [IsVia] p2: clearance=10
PlaneConnect [All] p1: planeconnectstyle=Relief reliefexpansion=10 reliefentries=4 reliefconductorwidth=10 reliefairgap=10
PolygonConnect PolygonConnect_via [isvia] p1: connectstyle=Direct reliefconductorwidth=10 reliefentries=4 polygonreliefangle="45 Angle" airgapwidth=10
PolygonConnect [All] p2: connectstyle=Relief reliefconductorwidth=10 reliefentries=4 polygonreliefangle="90 Angle" airgapwidth=5
RoutingVias ThermalPadVias [IsVia and InAnyComponent] p1: holewidth=8 width=22 viastyle="Through Hole" minholewidth=7.87 minwidth=19.68 maxholewidth=12.99 maxwidth=23.62
RoutingVias [All] p2: holewidth=8 width=22 viastyle="Through Hole" minholewidth=8 minwidth=17.72 maxholewidth=40 maxwidth=65
SilkToBoardRegionClearance [Not ((IsComment or IsDesignator) And (Hide <> 'False')) and not InRegion(1000,500,4000,800)] p1:
SilkToSilkClearance SilkToSilkClearance_Pb-FreeLogo [(HasFootprint('Pb-Free_Overlay_Medium') OR HasFootprint('Pb-Free_Overlay_Small')) vs (HasFootprint('Pb-Free_Overlay_Medium') OR HasFootprint('Pb-Free_Overlay_Small'))] p1: silktosilkclearance=0
SilkToSilkClearance [All] p2: silktosilkclearance=3
SilkToSolderMaskClearance SilkToComponentPadClearance [IsPad and InAnycomponent] p1: minsilkscreentomaskgap=3 clearancetoexposedcopper=TRUE
SilkToSolderMaskClearance "Silk to Solder Mask Opening" [All] p2: minsilkscreentomaskgap=3 clearancetoexposedcopper=FALSE
SolderMaskExpansion [All] p1: expansion=1.97 istentingtop=FALSE
Width [All] p1: maxlimit=50 minlimit=6 preferedwidth=6 minimp=50.000000 maximp=50.000000 favimp=50.000000 checkconnectedcopper=TRUE
13 further rules are at their usual default settings.

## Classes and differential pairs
component class MCU165E1_Support: C1 C2 C3 C4 C5 C95 D1 D2 R9 R10 R11 R12 R13 R16 R17 R18 R19 R20 R21 R22 R23 R92 S1 S2 S5 TP1 U2 U3 Y1
component class MCU165E1_XDS110_MCU: C76 C77 C78 C79 C80 C81 C82 C83 C84 C85 C86 C87 C88 C89 C90 D4 D5 R78 R79 R80 R81 R83 R84 R85 R86 R87 R88 R89 U16 Y2
component class Label: LBL1
component class Logo: Logo2 LogoX
component class MCU165E1_Hardware: FID1 FID2 FID3 FID4 FID5 FID6 LBL1 Logo1 Logo2 Logo3 LOGO4 LogoX ZZ1 ZZ2 ZZ3 ZZ4 ZZ5
component class FiducialMark: FID1 FID2 FID3 FID4 FID5 FID6
component class AssemblyNote: ZZ1 ZZ2 ZZ3 ZZ4 ZZ5
component class MCU165E1_ADC: C24 C25 C26 C27 C28 C29 C30 C31 C32 C33 C34 C35 C36 C37 C38 C39 C40 C41 C42 C43 C44 C45 C46 C47 C48 C49 C51 C52 C57 C96 C97 C98 R26 R27 R28 R29 R30 R31 R32 R33 R34 R35 R36 R37 R38 R39 R40 R41 R42 R43 R44 R45 R46 R48 R49 R94 R95 R96 S3 U1 U5 U6 U7 U8 U9
component class MCU165E1_GPIO: EC1 J1 R1 R2 R3 R4 R5 R6 R7 R8
component class MCU165E1_Emulator_Interface: C91 C92 C93 C94 R90 R91 S4 U17 U18
component class MCU165E1_Power: C6 C7 C10 C11 C12 C13 C14 C15 C19 C20 C21 C22 C23 D3 L1 L2 R24 R25 R93 TP2 TP3 TP4 TP5 TP6 TP10 U4
component class MCU165E1_XDS110_USB_Power: C62 C63 C64 C65 C66 C67 C68 C69 C70 C71 C72 C73 C74 D6 D7 D9 D10 J3 R62 R63 R64 R65 R66 R67 R68 R69 R70 R71 R72 R73 R74 R76 T1 TP7 TP8 TP9 TP11 U12 U13 U14 U15
differential pair MCU_PGA3_IN: +MCU_PGA3_IN_P -MCU_PGA3_IN_N
differential pair MCU_PGA2_IN: +MCU_PGA2_IN_P -MCU_PGA2_IN_N
differential pair MCU_PGA1_IN: +MCU_PGA1_IN_P -MCU_PGA1_IN_N
differential pair HSEC_PGA3_IN: +HSEC_PGA3_IN_P -HSEC_PGA3_IN_N
differential pair HSEC_PGA2_IN: +HSEC_PGA2_IN_P -HSEC_PGA2_IN_N
differential pair HSEC_PGA1_IN: +HSEC_PGA1_IN_P -HSEC_PGA1_IN_N
differential pair XDS_D: +XDS_D_P -XDS_D_N

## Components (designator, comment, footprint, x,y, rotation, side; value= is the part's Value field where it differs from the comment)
C1 "CL05C120JB5NNNC" 0402 1864.98,1093.03 r0 top value=12pF
C2 "885012205037" 0402 1029.66,1292.93 r180 top value=0.1uF
C3 "885012205037" 0402 2109.8,1637.42 r270 top value=0.1uF
C4 "885012205037" 0402 1811.79,1643.23 r270 top value=0.1uF
C5 "885012205037" 0402 1886.88,1589.99 r0 top value=0.1uF
C6 "CC0603KRX5R7BB106" FP-CC0603KRX5R7BB106_0603-MFG 1366.58,1147.23 r0 bottom value=10¦ÌF
C7 "885012105012" 0402 1650.35,1715.72 r180 top value=1uF
C10 "885012105012" 0402 1625.06,1623.37 r90 top value=1uF
C11 "885012106018" 0603 898.23,678.05 r270 top value=2.2uF
C12 "885012106018" 0603 1230.43,649.14 r180 bottom value=2.2uF
C13 "885012205037" 0402 1472.56,1147.65 r0 bottom value=0.1uF
C14 "885012205037" 0402 1655.97,1050.16 r0 bottom value=0.1uF
C15 "885012205037" 0402 1087.34,980.7 r270 bottom value=0.1uF
C19 "885012205037" 0402 1413.74,1262.11 r90 bottom value=0.1uF
C20 "885012205037" 0402 1655.97,1003.06 r0 bottom value=0.1uF
C21 "885012205037" 0402 1089.39,1077.98 r90 bottom value=0.1uF
C22 "885012106018" 0603 1994.08,997.41 r90 bottom value=2.2uF
C23 "885012106018" 0603 1768.2,982.77 r90 bottom value=2.2uF
C24 "885012206046" 0603 123,87.84 r270 bottom value=0.1uF
C25 "885012206046" 0603 375.17,163.71 r90 bottom value=0.1uF
C26 "C0603C104K8RACTU" 0603 464.06,81.64 r90 bottom value=0.1uF
C27 "885012206046" 0603 753.67,93.24 r270 bottom value=0.1uF
C28 "885012206046" 0603 612.87,81.64 r270 bottom value=0.1uF
C29 "C0603C331J5GACTU" 0603 39.81,497 r90 top value=330pF
C30 "C0603C331J5GACTU" 0603 94.27,497 r90 top value=330pF
C31 "C0603C331J5GACTU" 0603 227.5,497 r90 top value=330pF
C32 "C0603C331J5GACTU" 0603 173.03,497 r90 top value=330pF
C33 "C0603C331J5GACTU" 0603 291.49,497 r90 top value=330pF
C34 "C0603C331J5GACTU" 0603 612.88,497 r90 bottom value=330pF
C35 "C0603C331J5GACTU" 0603 494.42,497 r90 top value=330pF
C36 "C0603C331J5GACTU" 0603 741.34,497 r90 top value=330pF
C37 "C0603C331J5GACTU" 0603 686.88,497 r90 bottom value=330pF
C38 "C0603C331J5GACTU" 0603 741.34,497 r90 bottom value=330pF
C39 "C0603C331J5GACTU" 0603 558.42,497 r90 top value=330pF
C40 "C0603C331J5GACTU" 0603 612.88,497 r90 top value=330pF
C41 "C0603C331J5GACTU" 0603 815.34,497 r90 top value=330pF
C42 "C0603C331J5GACTU" 0603 815.34,497 r90 bottom value=330pF
C43 "C0603C331J5GACTU" 0603 558.42,497 r90 bottom value=330pF
C44 "C0603C331J5GACTU" 0603 686.88,497 r90 top value=330pF
C45 "C0603C331J5GACTU" 0603 173.03,497 r90 bottom value=330pF
C46 "C0603C331J5GACTU" 0603 439.95,497 r90 top value=330pF
C47 "C0603C331J5GACTU" 0603 439.95,497 r90 bottom value=330pF
C48 "C0603C331J5GACTU" 0603 265.85,497 r90 bottom value=330pF
C49 "C0603C331J5GACTU" 0603 345.96,497 r90 top value=330pF
C51 "C0603C331J5GACTU" 0603 320.31,497 r90 bottom value=330pF
C52 "C0603C331J5GACTU" 0603 869.81,497 r90 bottom value=330pF
C57 "885012106018" 0603 960.39,590.81 r180 top value=2.2uF
C62 "CL05B332KB5NNNC" FP-CL05B332KB5NNNC_0402-IPC_A -57.32,1634.5 r180 bottom value=3.3nF
C63 "CC0603KRX5R7BB106" FP-CC0603KRX5R7BB106_0603-MFG 397,1803.3 r90 bottom value=10¦ÌF
C64 "885012205037" 0402 457.69,1804.62 r90 bottom value=0.1uF
C65 "885012205037" 0402 1068.78,1671 r180 top value=0.1uF
C66 "CC0603KRX5R7BB106" FP-CC0603KRX5R7BB106_0603-MFG 1072,1728 r0 top value=10¦ÌF
C67 "885012205037" 0402 1064.51,1787 r180 top value=0.1uF
C68 "CC0603KRX5R7BB106" FP-CC0603KRX5R7BB106_0603-MFG 1423.65,1839.01 r270 top value=10¦ÌF
C69 "885012205037" 0402 1291.77,1705.05 r270 top value=0.1uF
C70 "CC0603KRX5R7BB106" FP-CC0603KRX5R7BB106_0603-MFG 1233,1712 r90 top value=10¦ÌF
C71 "885012205037" 0402 1515,1793.15 r0 top value=0.1uF
C72 "CC0603KRX5R7BB106" FP-CC0603KRX5R7BB106_0603-MFG -121,1160 r270 top value=10¦ÌF
C73 "CC0603KRX5R7BB106" FP-CC0603KRX5R7BB106_0603-MFG 197.48,1188.21 r180 top value=10¦ÌF
C74 "885012205037" 0402 -63,1159 r90 top value=0.1uF
C76 "885012205031" 0402 258.79,1353.83 r270 top value=0.01uF
C77 "885012205031" 0402 439.13,1396.21 r0 top value=0.01uF
C78 "885012205031" 0402 438.43,878.83 r90 top value=0.01uF
C79 "885012205031" 0402 199.13,1266.21 r0 top value=0.01uF
C80 "885012205037" 0402 382,881 r90 top value=0.1uF
C81 "885012205037" 0402 601.29,1237.85 r180 top value=0.1uF
C82 "885012105012" 0402 328,876 r90 top value=1uF
C83 "885012105012" 0402 600.51,1296.21 r180 top value=1uF
C84 "885012205031" 0402 591.75,1396.21 r0 top value=0.01uF
C85 "885012105013" 0402 466.77,1568.12 r90 bottom value=2.2uF
C86 "885012205037" 0402 416,1566 r90 bottom value=0.1uF
C87 "885012105012" 0402 509.77,1568.12 r90 bottom value=1uF
C88 "CL05C120JB5NNNC" 0402 23,1246.38 r270 bottom value=12pF
C89 "CL05C120JB5NNNC" 0402 23,1346.76 r90 bottom value=12pF
C90 "885012205037" 0402 -59.16,976.37 r270 bottom value=0.1uF
C91 "885012205037" 0402 706.51,1260.54 r180 top value=0.1uF
C92 "885012205037" 0402 1414.06,1391.94 r90 bottom value=0.1uF
C93 "885012205037" 0402 950,1274.62 r90 top value=0.1uF
C94 "C1812C100JHGACTU" 1812_180 -103.15,715 r90 bottom value=10pF
C95 "CL05C120JB5NNNC" 0402 1989.56,1212.4 r0 top value=12pF
C96 "885012206046" 0603 1072.44,790.96 r270 bottom value=0.1uF
C97 "885012206046" 0603 976.92,746.22 r90 bottom value=0.1uF
C98 "885012206046" 0603 1224.99,456.13 r0 bottom value=0.1uF
D1 "150080SS75000" WL-SMCW_RED_0805 2147.01,1831.78 r90 top value=Red
D2 "150080SS75000" WL-SMCW_RED_0805 2253.01,1831.79 r90 top value=Red
D3 "150080VS75000" WL-SMCW_Green_0805 1858.16,1488.9 r180 top value="Bright Green"
D4 "LTST-C170TBKT" LTST-C170TBKT_Blue 630,1797.54 r90 bottom value=Blue
D5 "LTST-C170TBKT" LTST-C170TBKT_Blue 552,1798.46 r90 bottom value=Blue
D6 "150080SS75000" WL-SMCW_RED_0805 1645,1831.8 r90 top value=Red
D7 "150080VS75000" WL-SMCW_Green_0805 110,1358 r270 top value="Bright Green"
D9 "1N5819HW-7-F" SOD-123 1096,1600 r180 top value=40V
D10 "1N5819HW-7-F" SOD-123 1095,1857 r180 top value=40V
EC1 "controlCARD-120HSEC_Edge" controlCARD-120HSEC_Edge 970.2,-245.16 r0 top locked
FID1 "Fiducial" Fiducial10-20 2270.24,1216.08 r90 bottom
FID2 "Fiducial" Fiducial10-20 2270.24,1216.08 r90 top
FID3 "Fiducial" Fiducial10-20 -170,386 r90 top
FID4 "Fiducial" Fiducial10-20 -212,1401.83 r90 bottom
FID5 "Fiducial" Fiducial10-20 -170,386 r90 bottom
FID6 "Fiducial" Fiducial10-20 -212,1401.83 r90 top
J1 "TMM-105-01-T-D" FP-TMM-105-01-T-D_HDR10-MFG 2248.37,490.74 r270 top
J3 "632723300011" Wurth_632_723_300_011 -291.83,1668.89 r270 top locked
L1 "60 ohm" 0805_HV 830.98,669.61 r270 top
L2 "60 ohm" 0805_HV 1884.95,965.68 r180 bottom
LBL1 "THT-14-423-10" Label_650x200 1669.86,494.42 r0 bottom locked
Logo1 "CE Mark" CE_Mark_5mm 2107.87,1525.73 r180 bottom locked
Logo2 "Texas Instruments" TI_Stacked_Overlay_Small 1502.11,100.52 r180 bottom
Logo3 "FCC disclaimer" FCC_disclaimer 767,745 r0 top
LOGO4 "WEEE logo" WEEE_Minimum 2097.88,1319.19 r180 bottom (schematic designator Logo4)
R1 "CRCW04024K70JNED" 0402 -10.38,82.06 r270 top value=4.7k
R2 "CRCW04024K70JNED" 0402 -10.38,82.06 r90 bottom value=4.7k
R3 "CRCW06030000Z0EA" 0603 2114.35,699.95 r90 top value=0
R4 "CRCW06030000Z0EA" 0603 2114.35,822.43 r90 top value=0
R5 "CRCW06030000Z0EA" 0603 2114.35,577.48 r90 top value=0
R6 "CRCW06030000Z0EA" 0603 2114.35,455 r90 top value=0
R7 "CRCW06030000Z0EA" 0603 2114.35,332.52 r90 top value=0
R8 "CRCW06030000Z0EA" 0603 2114.35,210.04 r90 top value=0
R9 "CRCW040256K0JNED" 0402 1759.8,694.73 r90 bottom value=56k
R10 "CRCW040256K0JNED" 0402 1846.88,809.65 r0 top value=56k
R11 "AC0402FR-0710KL" 0402 1673,869.37 r0 bottom value=10.0k
R12 "AC0402FR-0710KL" 0402 1673,777.57 r0 bottom value=10.0k
R13 "CRCW04022K20JNED" 0402 1673,823.47 r0 bottom value=2.2k
R16 "ERJ-2GE0R00X" 0402 1821.54,1069.72 r180 bottom value=0
R17 "ERJ-2GE0R00X" 0402 1749.02,1093.63 r90 bottom value=0
R18 "CRCW04022K20JNED" 0402 1029.66,1251.27 r180 top value=2.2k
R19 "CRCW0402820RJNED" 0402 2145,1851.28 r270 bottom value=820
R20 "CRCW0402820RJNED" 0402 2253.99,1851.28 r270 bottom value=820
R21 "CRCW04021M50JNED" 0402 2168.19,1513 r270 top value=1.5Meg
R22 "CRCW04021M50JNED" 0402 2243.61,1513 r270 top value=1.5Meg
R23 "ERJ-3GEY0R00V" 0603 1974,1630.32 r270 top value=0
R24 "CRCW08050000Z0EA" 0805_HV 1644.06,1501.37 r270 top value=0
R25 "CRCW0402510RJNED" 0402 1740.68,1508.37 r180 top value=510
R26 "CRCW06030000Z0EA" 0603 39.74,301.01 r270 top value=0
R27 "CRCW06030000Z0EA" 0603 94.21,301.01 r270 top value=0
R28 "CRCW06030000Z0EA" 0603 227.43,301.01 r270 top value=0
R29 "CRCW06030000Z0EA" 0603 869.74,497 r270 top value=0
R30 "CRCW06030000Z0EA" 0603 301.43,301.01 r270 top value=0
R31 "CRCW06030000Z0EA" 0603 612.82,301.01 r270 bottom value=0
R32 "CRCW06030000Z0EA" 0603 484.35,301.01 r270 top value=0
R33 "CRCW06030000Z0EA" 0603 741.28,301.01 r270 top value=0
R34 "CRCW06030000Z0EA" 0603 686.81,301.01 r270 bottom value=0
R35 "CRCW06030000Z0EA" 0603 741.28,301.01 r270 bottom value=0
R36 "CRCW06030000Z0EA" 0603 558.35,301.01 r270 top value=0
R37 "CRCW06030000Z0EA" 0603 612.82,301.01 r270 top value=0
R38 "CRCW06030000Z0EA" 0603 815.27,301.01 r270 top value=0
R39 "CRCW06030000Z0EA" 0603 815.27,301.01 r270 bottom value=0
R40 "CRCW06030000Z0EA" 0603 429.89,301.01 r270 bottom value=0
R41 "CRCW06030000Z0EA" 0603 686.81,301.01 r270 top value=0
R42 "CRCW06030000Z0EA" 0603 173.1,301.01 r270 bottom value=0
R43 "CRCW06030000Z0EA" 0603 429.89,301.01 r270 top value=0
R44 "CRCW06030000Z0EA" 0603 558.35,301.01 r270 bottom value=0
R45 "CRCW06030000Z0EA" 0603 484.35,301.01 r270 bottom value=0
R46 "CRCW06030000Z0EA" 0603 358.9,301.01 r270 bottom value=0
R48 "CRCW06030000Z0EA" 0603 304.44,301.01 r270 bottom value=0
R49 "CRCW06030000Z0EA" 0603 869.74,301.01 r270 bottom value=0
R62 "CRCW04021M00FKED" 0402 -62.62,1690 r0 bottom value=1.00Meg
R63 "ERJ-3GEY0R00V" 0603 298.3,1787 r0 bottom value=0
R64 "RC0603JR-075K1L" 0603 330,1586.5 r90 bottom value=5.1k
R65 "RC0603JR-075K1L" 0603 272,1586.5 r90 bottom value=5.1k
R66 "CRCW06032K20JNEA" 0603 1321.51,1700.16 r90 bottom value=2.2k
R67 "ERJ-3GEY0R00V" 0603 1466.54,1757.19 r180 bottom value=0
R68 "CRCW060310K0JNEA" 0603 1345,1703 r90 top value=10k
R69 "CRCW060310K0JNEA" 0603 1524,1847 r180 top value=10k
R70 "RC0603JR-074K7L" 0603 1378.29,1700.16 r90 bottom value=4.7k
R71 "RC0603FR-071KL" 0603 1719,1817 r270 top value=1.00k
R72 "RC0603FR-07430RL" 0603 1530.95,1543.21 r90 top value=430
R73 "RC0603JR-071K2L" 0603 1463.24,1542.91 r90 top value=1.2k
R74 "ERJ-3GEY0R00V" 0603 1392.47,1542.91 r90 top value=0
R76 "CRCW0402680RJNED" 0402 32,1349 r270 top value=680
R78 "CRCW04021K00JNED" 0402 197.67,1059 r90 top value=1.0k
R79 "CRCW04021K00JNED" 0402 244.95,1059 r90 top value=1.0k
R80 "CRCW04021K00JNED" 0402 292.79,1058.62 r90 top value=1.0k
R81 "CRCW04021K00JNED" 0402 337,1058.62 r90 top value=1.0k
R83 "CRCW0402100RJNED" 0402 259.63,1452.62 r270 top value=100
R84 "ERJ-2RKF4700X" 0402 611,1672.83 r270 bottom value=470
R85 "ERJ-2RKF4700X" 0402 568,1671.85 r270 bottom value=470
R86 "AC0402FR-0710KL" 0402 3.13,1081.83 r90 bottom value=10.0k
R87 "AC0402FR-0710KL" 0402 3.13,979.83 r90 bottom value=10.0k
R88 "CRCW04024K87FKED" 0402 261.66,879.58 r270 top value=4.87k
R89 "CRCW040251R0JNED" 0402 -56.87,1081.83 r90 bottom value=51
R90 "AC0402FR-0710KL" 0402 1147.44,1423.67 r180 top value=10.0k
R91 "AC0402FR-0710KL" 0402 1148.75,1355.99 r180 top value=10.0k
R92 "FC0603E50R0BTBST1" 0603 1965.8,1128.52 r90 top value=50
R93 "AC0402FR-0710KL" 0402 1740.68,1557.02 r0 top value=10.0k
R94 "CRCW06030000Z0EA" 0603 172.97,301.01 r270 top value=0
R95 "CRCW06030000Z0EA" 0603 355.89,301.01 r270 top value=0
R96 "CRCW06030000Z0EA" 0603 249.97,301.01 r270 bottom value=0
S1 "CAS-D20TA" SW_CAS-D20TA 1876.85,581.1 r0 top locked
S2 "1188E-1K2-V-TR" SW_1188E 1935.56,1825.43 r270 top locked
S3 "CHS-01TB" SW_CHS-01TB 999,379.47 r0 top
S4 "218-2LPST" SW_218-2LP 1380.81,1378.98 r0 top
S5 "CAS-220TA" SW_CAS-220TA 1857,951.26 r0 top
T1 "750315371" Wurth_750315371 745.74,1722 r180 top value=105uH
TP1 "TESTPOINT" TP_50MIL-25MILHOLE 2039.19,1661.86 r90 top
TP2 "TESTPOINT" TP_50MIL-25MILHOLE 1264,1789.57 r90 top
TP3 "TESTPOINT" TP_50MIL-25MILHOLE 2185.12,911.39 r270 top
TP4 "TESTPOINT" TP_50MIL-25MILHOLE 38.48,203.79 r90 top
TP5 "TESTPOINT" TP_50MIL-25MILHOLE 1939.77,206.88 r90 top
TP6 "TESTPOINT" TP_50MIL-25MILHOLE -100.4,497 r90 top
TP7 "TESTPOINT" TP_50MIL-25MILHOLE -194.73,1191 r90 top
TP8 "TESTPOINT" TP_50MIL-25MILHOLE -195.43,1000.36 r90 top
TP9 "TESTPOINT" TP_50MIL-25MILHOLE -106.87,898.05 r90 top
TP10 "TESTPOINT" TP_50MIL-25MILHOLE 2275.24,810.95 r90 top
TP11 "TESTPOINT" TP_50MIL-25MILHOLE 1754,1720 r90 top
U1 "TMS320F28P551SG5PZ" PZ0100A-MFG 1373.79,856.32 r0 top locked
U2 "TPS3703A4330DSERQ1" DSE0006A 1887.43,1655.99 r0 top
U3 "SN74LVC2G07DBVR" DBV0006A_N 2204,1647.71 r90 top
U4 "LP5912-3.3DRVR" DRV0006A 1706.28,1637.76 r90 top
U5 "TPD6E001RSER" RSE0010A 121,85 r0 top
U6 "TPD6E001RSER" RSE0010A 462.75,85 r0 top
U7 "TPD4E001QDBVRQ1" DBV0006A_N 296.89,132.24 r0 top
U8 "TPD6E001RSER" RSE0010A 753.82,85 r0 top
U9 "TPD6E001RSER" RSE0010A 611.07,85 r0 top
U12 "SN6505BDBVR" DBV0006A_L 329.8,1787 r180 top
U13 "TPD4E05U06DQAR" DQA0010A 263.14,1610.56 r90 top
U14 "TPS2113ADRBR" DRB0008B 1450.39,1692.88 r90 top
U15 "TLV70333DBVR" DBV0005A-MFG 40.8,1097.8 r0 top
U16 "MSP432E401YTPDT" PDT0128A 407.13,1169.21 r180 bottom locked
U17 "ISO7762DBQR" DBQ0016A_N 844,1108 r0 top
U18 "SN74ALVC244PWR" PW0020A_N 1240.91,1352.91 r90 bottom locked
Y1 "830108207209" FP-830108207209_SMT_CRYSTAL_3MM2_2MM5-MFG 1849.24,1183.26 r0 top
Y2 "830064296" FP-830064296_SMT4_3MM4_2MM7-MFG -99,1310 r90 bottom
ZZ1 "This Assembly Note is for PCB labels only" AssemblyNoteLabel -2000,-998 r0 top
ZZ2 "These assemblies are ESD sensitive, ESD precautions shall be observed." AssemblyNote -2000,-1116 r0 top
ZZ3 "These assemblies must be clean and free from flux and all contaminants. Use of no clean flux is not acceptable." AssemblyNote -1997,-1228 r0 top
ZZ4 "These assemblies must comply with workmanship standards IPC-A-610 Class 2, unless otherwise specified." AssemblyNote -1998,-1335 r0 top
ZZ5 "Clip off KEY pin 9 of J1 connector header" AssemblyNote -2005,-1451 r0 top

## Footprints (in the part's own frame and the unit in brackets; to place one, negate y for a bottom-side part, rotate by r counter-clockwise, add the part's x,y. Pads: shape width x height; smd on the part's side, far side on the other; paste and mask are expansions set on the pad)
0402 [mm] "0402 from SM-752 data"
  rect 0.8x0.6 smd: 1(-0.6,0) 2(0.6,0)
  silkscreen extent -1.22,-0.52 1.22,0.52, body extent -0.55,-0.3 0.55,0.3, height 0.6
0603 [mm] "0603 from SM-752 data"
  rect 1x0.95 smd: 1(-0.8,0) 2(0.8,0)
  silkscreen extent -1.52,-0.69 1.52,0.69, body extent -0.87,-0.47 0.87,0.47, height 1
0805_HV [mil] "0805 with 30mil clearance between pads"
  rect 50x63 smd: 1(-40,0) 2(40,0)
  silkscreen extent -74,-40 74,40, body extent -43,-29 43,29, height 57
1812_180 [mm] "SMT, 2-Leads, Body 4.5x3.2mm"
  rect 1.85x4.36 smd: 1(-2.53,0) 2(2.53,0)
  silkscreen extent -3.75,-2.48 3.75,2.48, body extent -2.43,-1.75 2.42,1.75, height 1.8
AssemblyNote [mil] "Assembly Note"
AssemblyNoteLabel [mil] "Assembly Note for PCB Labels"
CE_Mark_5mm [mil] "Minimum text height for CE Mark"
  silkscreen extent -138,-98 138,98
controlCARD-120HSEC_Edge [mm] "Edge Connector, 0.8mm, 60x2, pad numbers do not match Samtec datasheet"
  rect 0.55x2.8 smd paste-2.5 mask+0: 1(-23.6,2.4) 3(-22.8,2.4) 5(-22,2.4) 7(-21.2,2.4) 9(-20.4,2.4) 11(-19.6,2.4) 13(-18.8,2.4) 15(-18,2.4) 17(-17.2,2.4) 19(-16.4,2.4) 21(-15.6,2.4) 23(-14.8,2.4) 25(-14,2.4) 27(-13.2,2.4) 29(-12.4,2.4) 31(-11.6,2.4) 33(-10.8,2.4) 35(-10,2.4) 37(-9.2,2.4) 39(-8.4,2.4) 41(-7.6,2.4) 43(-6.8,2.4) 45(-6,2.4) 47(-5.2,2.4) 49(-4.4,2.4) 51(-3.6,2.4) 53(-2.8,2.4) 55(-2,2.4) 57(2,2.4) 59(2.8,2.4) 61(3.6,2.4) 63(4.4,2.4) 65(5.2,2.4) 67(6,2.4) 69(6.8,2.4) 71(7.6,2.4) 73(8.4,2.4) 75(9.2,2.4) 77(10,2.4) 79(10.8,2.4) 81(11.6,2.4) 83(12.4,2.4) 85(13.2,2.4) 87(14,2.4) 89(14.8,2.4) 91(15.6,2.4) 93(16.4,2.4) 95(17.2,2.4) 97(18,2.4) 99(18.8,2.4) 101(19.6,2.4) 103(20.4,2.4) 105(21.2,2.4) 107(22,2.4) 109(22.8,2.4) 111(23.6,2.4) 113(24.4,2.4) 115(25.2,2.4) 117(26,2.4) 119(26.8,2.4)
  rect 0.55x2.8 smd far side paste-2.5 mask+0: 2(-23.6,2.4) 4(-22.8,2.4) 6(-22,2.4) 8(-21.2,2.4) 10(-20.4,2.4) 12(-19.6,2.4) 14(-18.8,2.4) 16(-18,2.4) 18(-17.2,2.4) 20(-16.4,2.4) 22(-15.6,2.4) 24(-14.8,2.4) 26(-14,2.4) 28(-13.2,2.4) 30(-12.4,2.4) 32(-11.6,2.4) 34(-10.8,2.4) 36(-10,2.4) 38(-9.2,2.4) 40(-8.4,2.4) 42(-7.6,2.4) 44(-6.8,2.4) 46(-6,2.4) 48(-5.2,2.4) 50(-4.4,2.4) 52(-3.6,2.4) 54(-2.8,2.4) 56(-2,2.4) 58(2,2.4) 60(2.8,2.4) 62(3.6,2.4) 64(4.4,2.4) 66(5.2,2.4) 68(6,2.4) 70(6.8,2.4) 72(7.6,2.4) 74(8.4,2.4) 76(9.2,2.4) 78(10,2.4) 80(10.8,2.4) 82(11.6,2.4) 84(12.4,2.4) 86(13.2,2.4) 88(14,2.4) 90(14.8,2.4) 92(15.6,2.4) 94(16.4,2.4) 96(17.2,2.4) 98(18,2.4) 100(18.8,2.4) 102(19.6,2.4) 104(20.4,2.4) 106(21.2,2.4) 108(22,2.4) 110(22.8,2.4) 112(23.6,2.4) 114(24.4,2.4) 116(25.2,2.4) 118(26,2.4) 120(26.8,2.4)
DBQ0016A_N [mm] "SOP, 16-Leads, Body 4.9x3.9mm, Pitch 0.635mm, IPC Medium Density"
  oval 1.45x0.4 smd: 1(-2.725,2.222) 2(-2.725,1.587) 3(-2.725,0.953) 4(-2.725,0.318) 5(-2.725,-0.318) 6(-2.725,-0.953) 7(-2.725,-1.587) 8(-2.725,-2.222) 9(2.725,-2.222) 10(2.725,-1.587) 11(2.725,-0.953) 12(2.725,-0.318) 13(2.725,0.318) 14(2.725,0.953) 15(2.725,1.587) 16(2.725,2.222)
  silkscreen extent -3.35,-2.5 1.1,2.68, body extent -3.01,-2.45 3.01,2.45, height 1.63
DBV0005A-MFG [mm]
  rrect17% 1.1x0.6 smd paste+0 mask+0: 1(-1.3,0.95) 2(-1.3,0) 3(-1.3,-0.95) 4(1.3,-0.95) 5(1.3,0.95)
  silkscreen extent -1.77,-1.53 0.87,1.78, body extent -1.95,-1.78 1.95,1.78, height 0.25
DBV0006A_L [mm] "SOT23, 6-Leads, Body 2.9x1.6mm, Pitch 0.95mm, Lead Span 2.8mm, IPC High Density"
  rrect18% 0.8x0.55 smd: 1(-1.275,0.95) 2(-1.275,0) 3(-1.275,-0.95) 4(1.275,-0.95) 5(1.275,0) 6(1.275,0.95)
  silkscreen extent -1.55,-1.53 0.55,1.53, body extent -1.42,-1.46 1.42,1.46, height 1.12
DBV0006A_N [mm] "SOT23, 6-Leads, Body 2.9x1.6mm, Pitch 0.95mm, Lead Span 2.8mm, IPC Medium Density"
  rrect17% 1x0.6 smd: 1(-1.375,0.95) 2(-1.375,0) 3(-1.375,-0.95) 4(1.375,-0.95) 5(1.375,0) 6(1.375,0.95)
  silkscreen extent -1.67,-1.55 0.5,1.55, body extent -1.42,-1.46 1.42,1.46, height 1.12
DQA0010A [mm] "SON, 10-Leads, Body 1x2.5mm, Pitch 0.5mm, TI Recommended"
  rrect50% 0.565x0.2 smd: 1(-0.417,1) 2(-0.417,0.5) 4(-0.417,-0.5) 5(-0.417,-1) 6(0.417,-1) 7(0.417,-0.5) 9(0.417,0.5) 10(0.417,1)
  rrect28% 0.565x0.36 on Top Paste: 3(-0.417,0) 8(0.417,0)
  rrect25% 0.565x0.4 smd paste-0.2: 3(-0.417,0) 8(0.417,0)
  silkscreen extent -0.67,-1.45 0.55,1.45, body extent -0.55,-1.3 0.55,1.3, height 0.56
DRB0008B [mm] "SON, 8-Leads, Body 3x3mm, Pitch 0.65mm, Thermal Pad 2.4x1.65mm, TI Recommended"
  rrect33% 0.6x0.3 smd: 1(-1.4,0.975) 2(-1.4,0.325) 3(-1.4,-0.325) 4(-1.4,-0.975) 5(1.4,-0.975) 6(1.4,-0.325) 7(1.4,0.325) 8(1.4,0.975)
  rrect9% 1.47x1.06 on Top Paste: 9(0,0.63) 9(0,-0.63)
  rrect6% 1.65x2.4 smd paste-1.2: 9(0,0)
  silkscreen extent -1.73,-1.73 1.73,1.73, body extent 0,0 0,0, height 0.06
DRV0006A [mm] "SON, 6-Leads, Body 2x2mm, Pitch 0.65mm, Thermal Pad 1.6x1mm, TI Recommended"
  rrect33% 0.45x0.3 smd: 1(-0.975,0.65) 2(-0.975,0) 3(-0.975,-0.65) 4(0.975,-0.65) 5(0.975,0) 6(0.975,0.65)
  rrect14% 1x0.7 on Top Paste: 7(0,0.45) 7(0,-0.45)
  rrect10% 1x1.6 smd paste-0.5: 7(0,0)
  silkscreen extent -1.05,-1.2 1.05,1.2, body extent -1.05,-1.05 1.05,1.05, height 0.81
DSE0006A [mm] "TI recommended land pattern"
  rect 0.66x0.25 smd: 1(-0.62,0.5)
  rect 0.7x0.25 smd: 2(-0.6,0) 3(-0.6,-0.5) 4(0.6,-0.5) 5(0.6,0) 6(0.6,0.5)
  Top Signal Layer region: -0.3,0.625 -0.25,0.625 -0.15,0.525 -0.15,0.375 -0.3,0.375
  silkscreen extent -0.9,-0.92 0.9,0.92, body extent -0.77,-0.77 0.77,0.77, height 0.8
FCC_disclaimer [mil]
Fiducial10-20 [mm]
  round 1 smd mask+0.5: 1(0,0)
  Top Signal Layer keep-out circle w1.178: c0,0 r0.5
FP-830064296_SMT4_3MM4_2MM7-MFG [mm]
  rrect9% 1.4x1.15 smd paste+0 mask+0: 1(-1.1,-0.8) 2(1.1,-0.8) 3(1.1,0.8) 4(-1.1,0.8)
  silkscreen extent -2.17,-2.05 2.17,1.35, body extent -1.7,-1.35 1.7,1.35, height 0.8
FP-830108207209_SMT_CRYSTAL_3MM2_2MM5-MFG [mm]
  rrect9% 1.4x1.15 smd paste+0 mask+0: 1(-1.1,-0.8) 2(1.1,-0.8) 3(1.1,0.8) 4(-1.1,0.8)
  silkscreen extent -1.22,-2.05 0,1.35, body extent -1.9,-1.48 1.9,1.48, height 0.25
FP-CC0603KRX5R7BB106_0603-MFG [mm]
  rrect11% 0.9x0.9 smd paste+0 mask+0: 1(-0.7,0) 2(0.7,0)
  silkscreen extent -0.9,-0.82 0.9,0.82, body extent -0.8,-0.4 0.8,0.4, height 1
FP-CL05B332KB5NNNC_0402-IPC_A [mil]
  rrect15% 28.16x26.48 smd paste+0 mask+0: 1(-18.84,0) 2(18.84,0)
  silkscreen extent -33,-29 33,29, body extent -20,-10 20,10, height 22
FP-TMM-105-01-T-D_HDR10-MFG [mm]
  rrect7% 1.39x1.39 hole 0.89 paste-1000 mask+0: 1(-4,-1)
  round 1.39 hole 0.89 paste-1000 mask+0: 2(-4,1) 3(-2,-1) 4(-2,1) 5(0,-1) 6(0,1) 7(2,-1) 8(2,1) 9(4,-1) 10(4,1)
  body extent -5.1,-2.13 5.1,2.13, height 0.25
Label_650x200 [mil] "Thermal Transfer Label"
  round 1 on Mech14: 0(0,0)
  silkscreen extent -325,-100 325,100, body extent -325,-100 325,100, height 1
LTST-C170TBKT_Blue [mm] "LITE-ON"
  rect 1.2x1.2 smd: 1(-1.05,0) 2(1.05,0)
  silkscreen extent -1.6,-1 2.2,1, body extent -1.05,-0.67 1.05,0.67, height 1.2
PDT0128A [mm] "Thin QFP, 128-Leads, Body 14x14mm, Pitch 0.4mm"
  oval 1.4x0.2 smd: 1(-7.7,6.2) 2(-7.7,5.8) 3(-7.7,5.4) 4(-7.7,5) 5(-7.7,4.6) 6(-7.7,4.2) 7(-7.7,3.8) 8(-7.7,3.4) 9(-7.7,3) 10(-7.7,2.6) 11(-7.7,2.2) 12(-7.7,1.8) 13(-7.7,1.4) 14(-7.7,1) 15(-7.7,0.6) 16(-7.7,0.2) 17(-7.7,-0.2) 18(-7.7,-0.6) 19(-7.7,-1) 20(-7.7,-1.4) 21(-7.7,-1.8) 22(-7.7,-2.2) 23(-7.7,-2.6) 24(-7.7,-3) 25(-7.7,-3.4) 26(-7.7,-3.8) 27(-7.7,-4.2) 28(-7.7,-4.6) 29(-7.7,-5) 30(-7.7,-5.4) 31(-7.7,-5.8) 32(-7.7,-6.2) 65(7.7,-6.2) 66(7.7,-5.8) 67(7.7,-5.4) 68(7.7,-5) 69(7.7,-4.6) 70(7.7,-4.2) 71(7.7,-3.8) 72(7.7,-3.4) 73(7.7,-3) 74(7.7,-2.6) 75(7.7,-2.2) 76(7.7,-1.8) 77(7.7,-1.4) 78(7.7,-1) 79(7.7,-0.6) 80(7.7,-0.2) 81(7.7,0.2) 82(7.7,0.6) 83(7.7,1) 84(7.7,1.4) 85(7.7,1.8) 86(7.7,2.2) 87(7.7,2.6) 88(7.7,3) 89(7.7,3.4) 90(7.7,3.8) 91(7.7,4.2) 92(7.7,4.6) 93(7.7,5) 94(7.7,5.4) 95(7.7,5.8) 96(7.7,6.2)
  oval 0.2x1.4 smd: 33(-6.2,-7.7) 34(-5.8,-7.7) 35(-5.4,-7.7) 36(-5,-7.7) 37(-4.6,-7.7) 38(-4.2,-7.7) 39(-3.8,-7.7) 40(-3.4,-7.7) 41(-3,-7.7) 42(-2.6,-7.7) 43(-2.2,-7.7) 44(-1.8,-7.7) 45(-1.4,-7.7) 46(-1,-7.7) 47(-0.6,-7.7) 48(-0.2,-7.7) 49(0.2,-7.7) 50(0.6,-7.7) 51(1,-7.7) 52(1.4,-7.7) 53(1.8,-7.7) 54(2.2,-7.7) 55(2.6,-7.7) 56(3,-7.7) 57(3.4,-7.7) 58(3.8,-7.7) 59(4.2,-7.7) 60(4.6,-7.7) 61(5,-7.7) 62(5.4,-7.7) 63(5.8,-7.7) 64(6.2,-7.7) 97(6.2,7.7) 98(5.8,7.7) 99(5.4,7.7) 100(5,7.7) 101(4.6,7.7) 102(4.2,7.7) 103(3.8,7.7) 104(3.4,7.7) 105(3,7.7) 106(2.6,7.7) 107(2.2,7.7) 108(1.8,7.7) 109(1.4,7.7) 110(1,7.7) 111(0.6,7.7) 112(0.2,7.7) 113(-0.2,7.7) 114(-0.6,7.7) 115(-1,7.7) 116(-1.4,7.7) 117(-1.8,7.7) 118(-2.2,7.7) 119(-2.6,7.7) 120(-3,7.7) 121(-3.4,7.7) 122(-3.8,7.7) 123(-4.2,7.7) 124(-4.6,7.7) 125(-5,7.7) 126(-5.4,7.7) 127(-5.8,7.7) 128(-6.2,7.7)
  silkscreen extent -7.7,-6.3 6.3,6.99, body extent 0,0 0,0, height 0.52
PW0020A_N [mm] "TSOP, 20-Leads, Body 6.5x4.4mm, Pitch 0.65mm, IPC Medium Density"
  oval 1.4x0.45 smd: 1(-2.95,2.925) 2(-2.95,2.275) 3(-2.95,1.625) 4(-2.95,0.975) 5(-2.95,0.325) 6(-2.95,-0.325) 7(-2.95,-0.975) 8(-2.95,-1.625) 9(-2.95,-2.275) 10(-2.95,-2.925) 11(2.95,-2.925) 12(2.95,-2.275) 13(2.95,-1.625) 14(2.95,-0.975) 15(2.95,-0.325) 16(2.95,0.325) 17(2.95,0.975) 18(2.95,1.625) 19(2.95,2.275) 20(2.95,2.925)
  Top Overlay keep-out lines w0.2: -1.85,-3.3 1.85,-3.3
  silkscreen extent -3.5,-3.3 1.85,3.4, body extent 0,0 0,0, height 0.62
PZ0100A-MFG [mm] "Recommended Land Pattern"
  rrect33% 1.6x0.3 smd paste-1000 mask+0: 1(-7.6,6) 2(-7.6,5.5) 3(-7.6,5) 4(-7.6,4.5) 5(-7.6,4) 6(-7.6,3.5) 7(-7.6,3) 8(-7.6,2.5) 9(-7.6,2) 10(-7.6,1.5) 11(-7.6,1) 12(-7.6,0.5) 13(-7.6,0) 14(-7.6,-0.5) 15(-7.6,-1) 16(-7.6,-1.5) 17(-7.6,-2) 18(-7.6,-2.5) 19(-7.6,-3) 20(-7.6,-3.5) 21(-7.6,-4) 22(-7.6,-4.5) 23(-7.6,-5) 24(-7.6,-5.5) 25(-7.6,-6) 51(7.6,-6) 52(7.6,-5.5) 53(7.6,-5) 54(7.6,-4.5) 55(7.6,-4) 56(7.6,-3.5) 57(7.6,-3) 58(7.6,-2.5) 59(7.6,-2) 60(7.6,-1.5) 61(7.6,-1) 62(7.6,-0.5) 63(7.6,0) 64(7.6,0.5) 65(7.6,1) 66(7.6,1.5) 67(7.6,2) 68(7.6,2.5) 69(7.6,3) 70(7.6,3.5) 71(7.6,4) 72(7.6,4.5) 73(7.6,5) 74(7.6,5.5) 75(7.6,6)
  rrect33% 0.3x1.6 smd paste-1000 mask+0: 26(-6,-7.6) 27(-5.5,-7.6) 28(-5,-7.6) 29(-4.5,-7.6) 30(-4,-7.6) 31(-3.5,-7.6) 32(-3,-7.6) 33(-2.5,-7.6) 34(-2,-7.6) 35(-1.5,-7.6) 36(-1,-7.6) 37(-0.5,-7.6) 38(0,-7.6) 39(0.5,-7.6) 40(1,-7.6) 41(1.5,-7.6) 42(2,-7.6) 43(2.5,-7.6) 44(3,-7.6) 45(3.5,-7.6) 46(4,-7.6) 47(4.5,-7.6) 48(5,-7.6) 49(5.5,-7.6) 50(6,-7.6) 76(6,7.6) 77(5.5,7.6) 78(5,7.6) 79(4.5,7.6) 80(4,7.6) 81(3.5,7.6) 82(3,7.6) 83(2.5,7.6) 84(2,7.6) 85(1.5,7.6) 86(1,7.6) 87(0.5,7.6) 88(0,7.6) 89(-0.5,7.6) 90(-1,7.6) 91(-1.5,7.6) 92(-2,7.6) 93(-2.5,7.6) 94(-3,7.6) 95(-3.5,7.6) 96(-4,7.6) 97(-4.5,7.6) 98(-5,7.6) 99(-5.5,7.6) 100(-6,7.6)
  silkscreen extent -9.07,-7.1 7.1,7.1, body extent -8.5,-8.5 8.5,8.5, height 0.25
RSE0010A [mm] "QFN, 10-Leads, Body 1.5x2mm, Pitch 0.5mm, TI Recommended"
  rect 0.55x0.2 smd: 1(-0.675,0.75) 2(-0.675,0.25) 3(-0.675,-0.25) 4(-0.675,-0.75) 6(0.675,-0.75) 7(0.675,-0.25) 8(0.675,0.25) 9(0.675,0.75)
  rect 0.3x0.6 smd: 5(0,-0.9) 10(0,0.9)
  silkscreen extent -1.07,-1.17 0.77,1.18, body extent -0.77,-1.02 0.78,1.03, height 0.61
SOD-123 [mm] "On Semi recommended land pattern"
  rect 0.915x1.22 smd: 1(-1.637,0) 2(1.637,0)
  silkscreen extent -2.74,-1.17 2.03,1.17, body extent -1.93,-0.9 1.93,0.9, height 1.35
SW_218-2LP [mm] "SMD, 4-Leads, Body 3.71x5.8mm, Pitch 1.27mm"
  rect 1.27x0.76 smd: 1(-3.81,0.635) 2(-3.81,-0.635) 3(3.81,-0.635) 4(3.81,0.635)
  silkscreen extent -2.9,-1.86 2.9,2.09, body extent -4.22,-1.86 4.22,1.85, height 2.62
SW_1188E [mm] "SMD, 4-Leads, Body 7.8x3.5mm"
  rrect10% 1x1.45 smd: 1(-1.1,3.375) 2(-1.1,-3.375)
  rrect11% 1.3x0.9 smd: 3(0.7,2.1) 4(0.7,-2.1)
  round 0 hole 0.9 unplated: ""(-0.35,1.15) ""(-0.35,-1.15)
  silkscreen extent -1.98,-2.28 0.95,2.28, body extent -2.55,-3.9 1.05,3.9, height 3.5
SW_CAS-220TA [mm] "COPAL ELECTRONICS"
  rect 1.6x1 smd: 1(-1.85,1.75) 2(-1.85,0) 3(-1.85,-1.75) 4(1.85,1.75) 5(1.85,0) 6(1.85,-1.75)
  silkscreen extent -2.1,-2.9 2,3.7, body extent -2.1,-2.85 2.1,2.85, height 2.51
SW_CAS-D20TA [mm] "SMD, 6-Leads, Body 5.4x3.9mm, Pitch 1.75mm"
  rect 1.6x1 smd: 1(-1.85,1.75) 2(-1.85,0) 3(-1.85,-1.75) 4(1.85,1.75) 5(1.85,0) 6(1.85,-1.75)
  silkscreen extent -1.95,-2.7 1.95,2.9, body extent -2.1,-2.7 2.1,2.7, height 2.5
SW_CHS-01TB [mm] "CHS Recommended footprint"
  rect 1x1.27 smd: 1(0,3.81) 2(0,-3.81)
  silkscreen extent -1.8,-4.05 1.3,4.05, body extent -1.25,-4 1.25,4, height 2.51
TI_Stacked_Overlay_Small [mil]
  silkscreen extent -418,-98 418,98
TP_50MIL-25MILHOLE [mil]
  round 50 hole 25: 1(0,0)
WEEE_Minimum [mil] "WEEElie bin"
  silkscreen extent -95,-172 99,104
WL-SMCW_Green_0805 [mm] "SMD, 2-Leads, Body 2x1.25mm"
  rect 1.1x1.2 smd: 1(-1.05,0) 2(1.05,0)
  silkscreen extent -2.4,-1.1 1.5,1.1, body extent -1,-0.62 1,0.63, height 0.7
WL-SMCW_RED_0805 [mm] "SMD, 2-Leads, Body 1.6x0.8mm"
  rect 1.1x1.2 smd: 1(-1.05,0) 2(1.05,0)
  silkscreen extent -2.4,-1.1 1.5,1.1, body extent -1,-0.62 1,0.63, height 0.7
Wurth_632_723_300_011 [mm] "Connector, Receptacle, USB Type C, R/A"
  rect 0.3x1.2 smd: A1(-2.75,10.58) A2(-2.25,10.58) A3(-1.75,10.58) A4(-1.25,10.58) A5(-0.75,10.58) A6(-0.25,10.58) A7(0.25,10.58) A8(0.75,10.58) A9(1.25,10.58) A10(1.75,10.58) A11(2.25,10.58) A12(2.75,10.58)
  round 0.55 hole 0.4: B1(2.8,9.32) B2(2.4,8.62) B3(1.6,8.62) B4(1.2,9.32) B5(0.8,8.62) B6(0.4,9.32) B7(-0.4,9.32) B8(-0.8,8.62) B9(-1.2,9.32) B10(-1.6,8.62) B11(-2.4,8.62) B12(-2.8,9.32) M1(2,9.32) M2(-2,9.32)
  rrect100% 1x1.6 hole 0.6 slot 1.2 at 90 deg: S1(-4.27,8.18) S2(-4.27,3.45) S3(4.27,3.45) S4(4.27,8.18)
  silkscreen extent -4.37,0.15 4.37,10.36, body extent -4.37,-0.96 4.37,10.83, height 3.07
Wurth_750315371 [mm] "SMD, Body 12.6x8.3mm, Pitch 2.54mm"
  rect 1.83x1.09 smd: 1(-5.62,2.54) 2(-5.62,0) 3(-5.62,-2.54) 4(5.62,-2.54) 5(5.62,0) 6(5.62,2.54)
  silkscreen extent -6.3,-4.15 6.3,4.4, body extent -6.35,-4.2 6.35,4.2, height 4.11

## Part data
C1 C88 C89 C95: library part CMP-0006345-2, "CAP, CERM, 12 pF, 50 V, +/- 5%, C0G/NP0, 0402", Cap_Case=0402, Manufacturer="Samsung Electro-Mechanics", Supplier Part Number 1=1276-1178-1-ND, TempCo=C0G/NP0, Tolerance_%=5%, Value1=Unknown, Value2=50V, ValueDisplayed=12pF
C2 C3 C4 C5 C13 C14 C15 C19 C20 C21 C64 C65 C67 C69 C71 C74 C80 C81 C86 C90 C91 C92 C93: library part CMP-0006228-2, "CAP, CERM, 0.1 uF, 16 V, +/- 10%, X7R, 0402", Cap_Case=0402, Manufacturer="Wurth Elektronik", Supplier Part Number 1=732-7532-1-ND, TempCo=X7R, Tolerance_%=10%, Value1=Unknown, Value2=16V, ValueDisplayed=0.1uF
C6 C63 C66 C68 C70 C72 C73: library part CMP-0001560-1, "Multilayer Ceramic Capacitors 10uF 16V X5R 10% SMD 0603 85¡ãC Paper T/R - Tape an", Digikey Part Number=311-3486-1-ND, Manufacturer=Yageo, Mouser Part Number=603-CC0603KRX57BB106, Operating Temperature Range="-55¡ãC to +85?", TempCo=15%, Temperature Characteristic=X5R, Tolerance_%=10%, ValueDisplayed=10uF
C7 C10 C82 C83 C87: library part CMP-0064924-2, "CAP, CERM, 1 uF, 10 V,+/- 20%, X5R, 0402", Cap_Case=0402, Manufacturer="Wurth Elektronik", Supplier Part Number 1=732-7489-1-ND, TempCo=X5R, Tolerance_%=20%, Value1=Unknown, Value2=10V, ValueDisplayed=1uF
C11 C12 C22 C23 C57: library part CMP-0006825-5, "CAP, CERM, 2.2 uF, 16 V, +/- 20%, X5R, 0603", Cap_Case=0603, Manufacturer="Wurth Elektronik", Supplier Part Number 1=732-7915-1-ND, TempCo=X5R, Tolerance_%=20%, Value1=Unknown, Value2=16V, ValueDisplayed=2.2uF
C24 C25 C27 C28 C96 C97 C98: library part CMP-0006829-4, "CAP, CERM, 0.1 uF, 16 V, +/- 10%, X7R, 0603", Cap_Case=0603, Manufacturer="Wurth Elektronik", Supplier Part Number 1=710-885012206046, TempCo=X7R, Tolerance_%=10%, Value1=Unknown, Value2=16V, ValueDisplayed=0.1uF
C26: library part CMP-0006862-5, "CAP, CERM, 0.1 uF, 10 V, +/- 10%, X7R, 0603", Cap_Case=0603, Manufacturer=Kemet, Supplier Part Number 1=399-1095-1-ND, TempCo=X7R, Tolerance_%=10%, Value1=Unknown, Value2=10V, ValueDisplayed=0.1uF
C29 C30 C31 C32 C33 C34 C35 C36 C37 C38 C39 C40 C41 C42 C43 C44 C45 C46 C47 C48 C49 C51 C52: library part CMP-0006920-4, "CAP, CERM, 330 pF, 50 V, +/- 5%, C0G/NP0, 0603", Cap_Case=0603, Manufacturer=Kemet, Supplier Part Number 1=399-1068-1-ND, TempCo=C0G/NP0, Tolerance_%=5%, Value1=Unknown, Value2=50V, ValueDisplayed=330pF
C62: library part CMP-0092214-1, "Cap Ceramic 3.3nF 50V X7R ¡À10% SMD 0402 +125¡ãC Paper T/R", Manufacturer=Samsung, Operating Temperature Range="-55¡ãC to +125?", TempCo=15%, Temperature Characteristic=X7R, Tolerance_%=10%, ValueDisplayed=3.3nF
C76 C77 C78 C79 C84: library part CMP-0006227-2, "CAP, CERM, 0.01 uF, 16 V, +/- 10%, X7R, 0402", Cap_Case=0402, Manufacturer="Wurth Elektronik", Supplier Part Number 1=710-885012205031, TempCo=X7R, Tolerance_%=10%, Value1=Unknown, Value2=16V, ValueDisplayed=0.01uF
C85: library part CMP-0006222-2, "CAP, CERM, 2.2 uF, 10 V, +/- 20%, X5R, 0402", Cap_Case=0402, Manufacturer="Wurth Elektronik", Supplier Part Number 1=710-885012105013, TempCo=X5R, Tolerance_%=20%, Value1=Unknown, Value2=10V, ValueDisplayed=2.2uF
C94: library part CMP-0082066-1, "CAP, CERM, 10 pF, 3000 V,+/- 5%, C0G/NP0, AEC-Q200 Grade 1, 1812", Cap_Case=1812, Manufacturer=Kemet, Supplier Part Number 1=399-7113-1-ND, TempCo=C0G/NP0, Tolerance_%=5%, Value2=3000V, ValueDisplayed=10pF
D1 D2 D6: library part CMP-0002951-3, "LED, Red, SMD", Color=Red, Manufacturer="Wurth Elektronik", Power_TotalModule=72mW, Value1=0.072W, Value2=1.9V
D3 D7: library part CMP-0002960-2, "LED, Bright Green, SMD", Color="Bright Green", Manufacturer="Wurth Elektronik", Power_TotalModule=72mW, Supplier Part Number 1=732-4986-1-ND, Value1=0.072W, Value2=2V
D4 D5: library part CMP-0002889-2, "LED, Blue, SMD", Color=Blue, Manufacturer=Lite-On, Value1=W, Value2=3.3V
D9 D10: library part CMP-0028360-2, "Diode, Schottky, 40 V, 1 A, SOD-123", Manufacturer="Diodes Inc.", Value1=1A, Value2=0.45V
EC1: library part CMP-0003813-2, "C2000 controlCARD-120HSEC Edge Connector for Samtec HSEC8-160-01-L-DV-A-BL", Manufacturer=Any
FID1 FID2 FID3 FID4 FID5 FID6: library part CMP-0077181-1, "Fiducial mark.  There is nothing to buy or mount.", Manufacturer=N/A
J1: library part CMP-0086568-1, "Board-To-Board Connector, TMM Series, 10 Contacts, Header, 2 mm, Through Hole, 2 Rows", Current_A=3.2A, Manufacturer=Samtec, Voltage_V=281V
J3: library part CMP-0080891-1, "Connector, Receptacle, USB Type C, R/A", Color=Black, Current_A=3A, Manufacturer="Wurth Elektronik", Supplier Part Number 1=732-9618-1-ND, Voltage_V=5V
L1 L2: library part CMP-0003093-1, "Ferrite Bead, 60 ohm @ 100 MHz, 3 A, 0805", Manufacturer="Wurth Elektronik", PartNumber=742792063, Supplier Part Number 1=732-1612-1-ND, Value1="0.025 ohm", Value2=3A
LBL1: library part CMP-0003625-1, "Thermal Transfer Printable Labels, 0.650\" W x 0.200\" H - 10,000 per roll", Manufacturer=Brady, Supplier Part Number 1=97C5133
Logo1: library part CMP-0074844-1
Logo2: library part CMP-0074838-1, "Texas Instrument Corporate Signature"
Logo3: library part CMP-0074847-1, "FCC_disclaimer"
LOGO4: library part CMP-0074769-1
R1 R2: library part CMP-0026938-5, "RES, 4.7 k, 5%, 0.063 W, AEC-Q200 Grade 0, 0402", Manufacturer=Vishay-Dale, Power_W=63mW, Supplier Part Number 1=541-4.7KJCT-ND, TempCo="200 ppm/C", Tolerance_%=5%, Value2=0.063W, Value_Code=4k70, ValueDisplayed=4.7k
R3 R4 R5 R6 R7 R8 R26 R27 R28 R29 R30 R31 R32 R33 R34 R35 R36 R37 R38 R39 R40 R41 R42 R43 R44 R45 R46 R48 R49 R94 R95 R96: library part CMP-0025697-4, "RES, 0, 5%, 0.1 W, AEC-Q200 Grade 0, 0603", Manufacturer=Vishay-Dale, Power_W=100mW, Supplier Part Number 1=541-0.0GCT-ND, TempCo="200 ppm/C", Tolerance_%=5%, Value2=0.1W, Value_Code=0000, ValueDisplayed=0
R9 R10: library part CMP-0026949-3, "RES, 56 k, 5%, 0.063 W, AEC-Q200 Grade 0, 0402", Manufacturer=Vishay-Dale, Power_W=63mW, Supplier Part Number 1=541-56KJCT-ND, TempCo="200 ppm/C", Tolerance_%=5%, Value2=0.063W, Value_Code=56k0, ValueDisplayed=56k
R11 R12 R86 R87 R90 R91 R93: library part CMP-0077731-1, "RES, 10.0 k, 1%, 0.063 W, AEC-Q200 Grade 0, 0402", Manufacturer="Yageo America", Power_W=63mW, Supplier Part Number 1=YAG3436CT-ND, TempCo="100 ppm/C", Tolerance_%=1%, Value2=0.063W, Value_Code=10k0, ValueDisplayed=10.0k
